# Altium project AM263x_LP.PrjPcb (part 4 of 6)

## Sheet PROC111_Ehernet_PHY_2.SchDoc
size 431 x 279 mm; Date: Not shown in title block; ApprovedBy: Not shown in title block; CheckedBy: Not shown in title block; Author: Not shown in title block; CompanyName: Not shown in title block; Engineer: Not shown in title block; Organization: Not shown in title block; Address1: Not shown in title block; Address2: Not shown in title block; Address3: Not shown in title block; Address4: Not shown in title block; DocumentNumber: 16; Revision: Use project parameter SCH_Rev; SheetNumber: 16; SheetTotal: 24; PageSetup: Record=PageOptions¦CenterHorizontal=True¦CenterVertical=True¦PrintScale=1.00¦XCorrection=1.00¦YCorrection=1.00¦PrintKind=0¦BorderSize=5000000¦LeftOffset=0¦BottomOffset=0¦Orientation=2¦PaperLength=1000¦PaperWidth=1000¦Scale=100¦PaperSource=15¦PrintQuality=600¦MediaType=1¦DitherType=10¦PaperKind=Letter¦PrintScaleMode=1
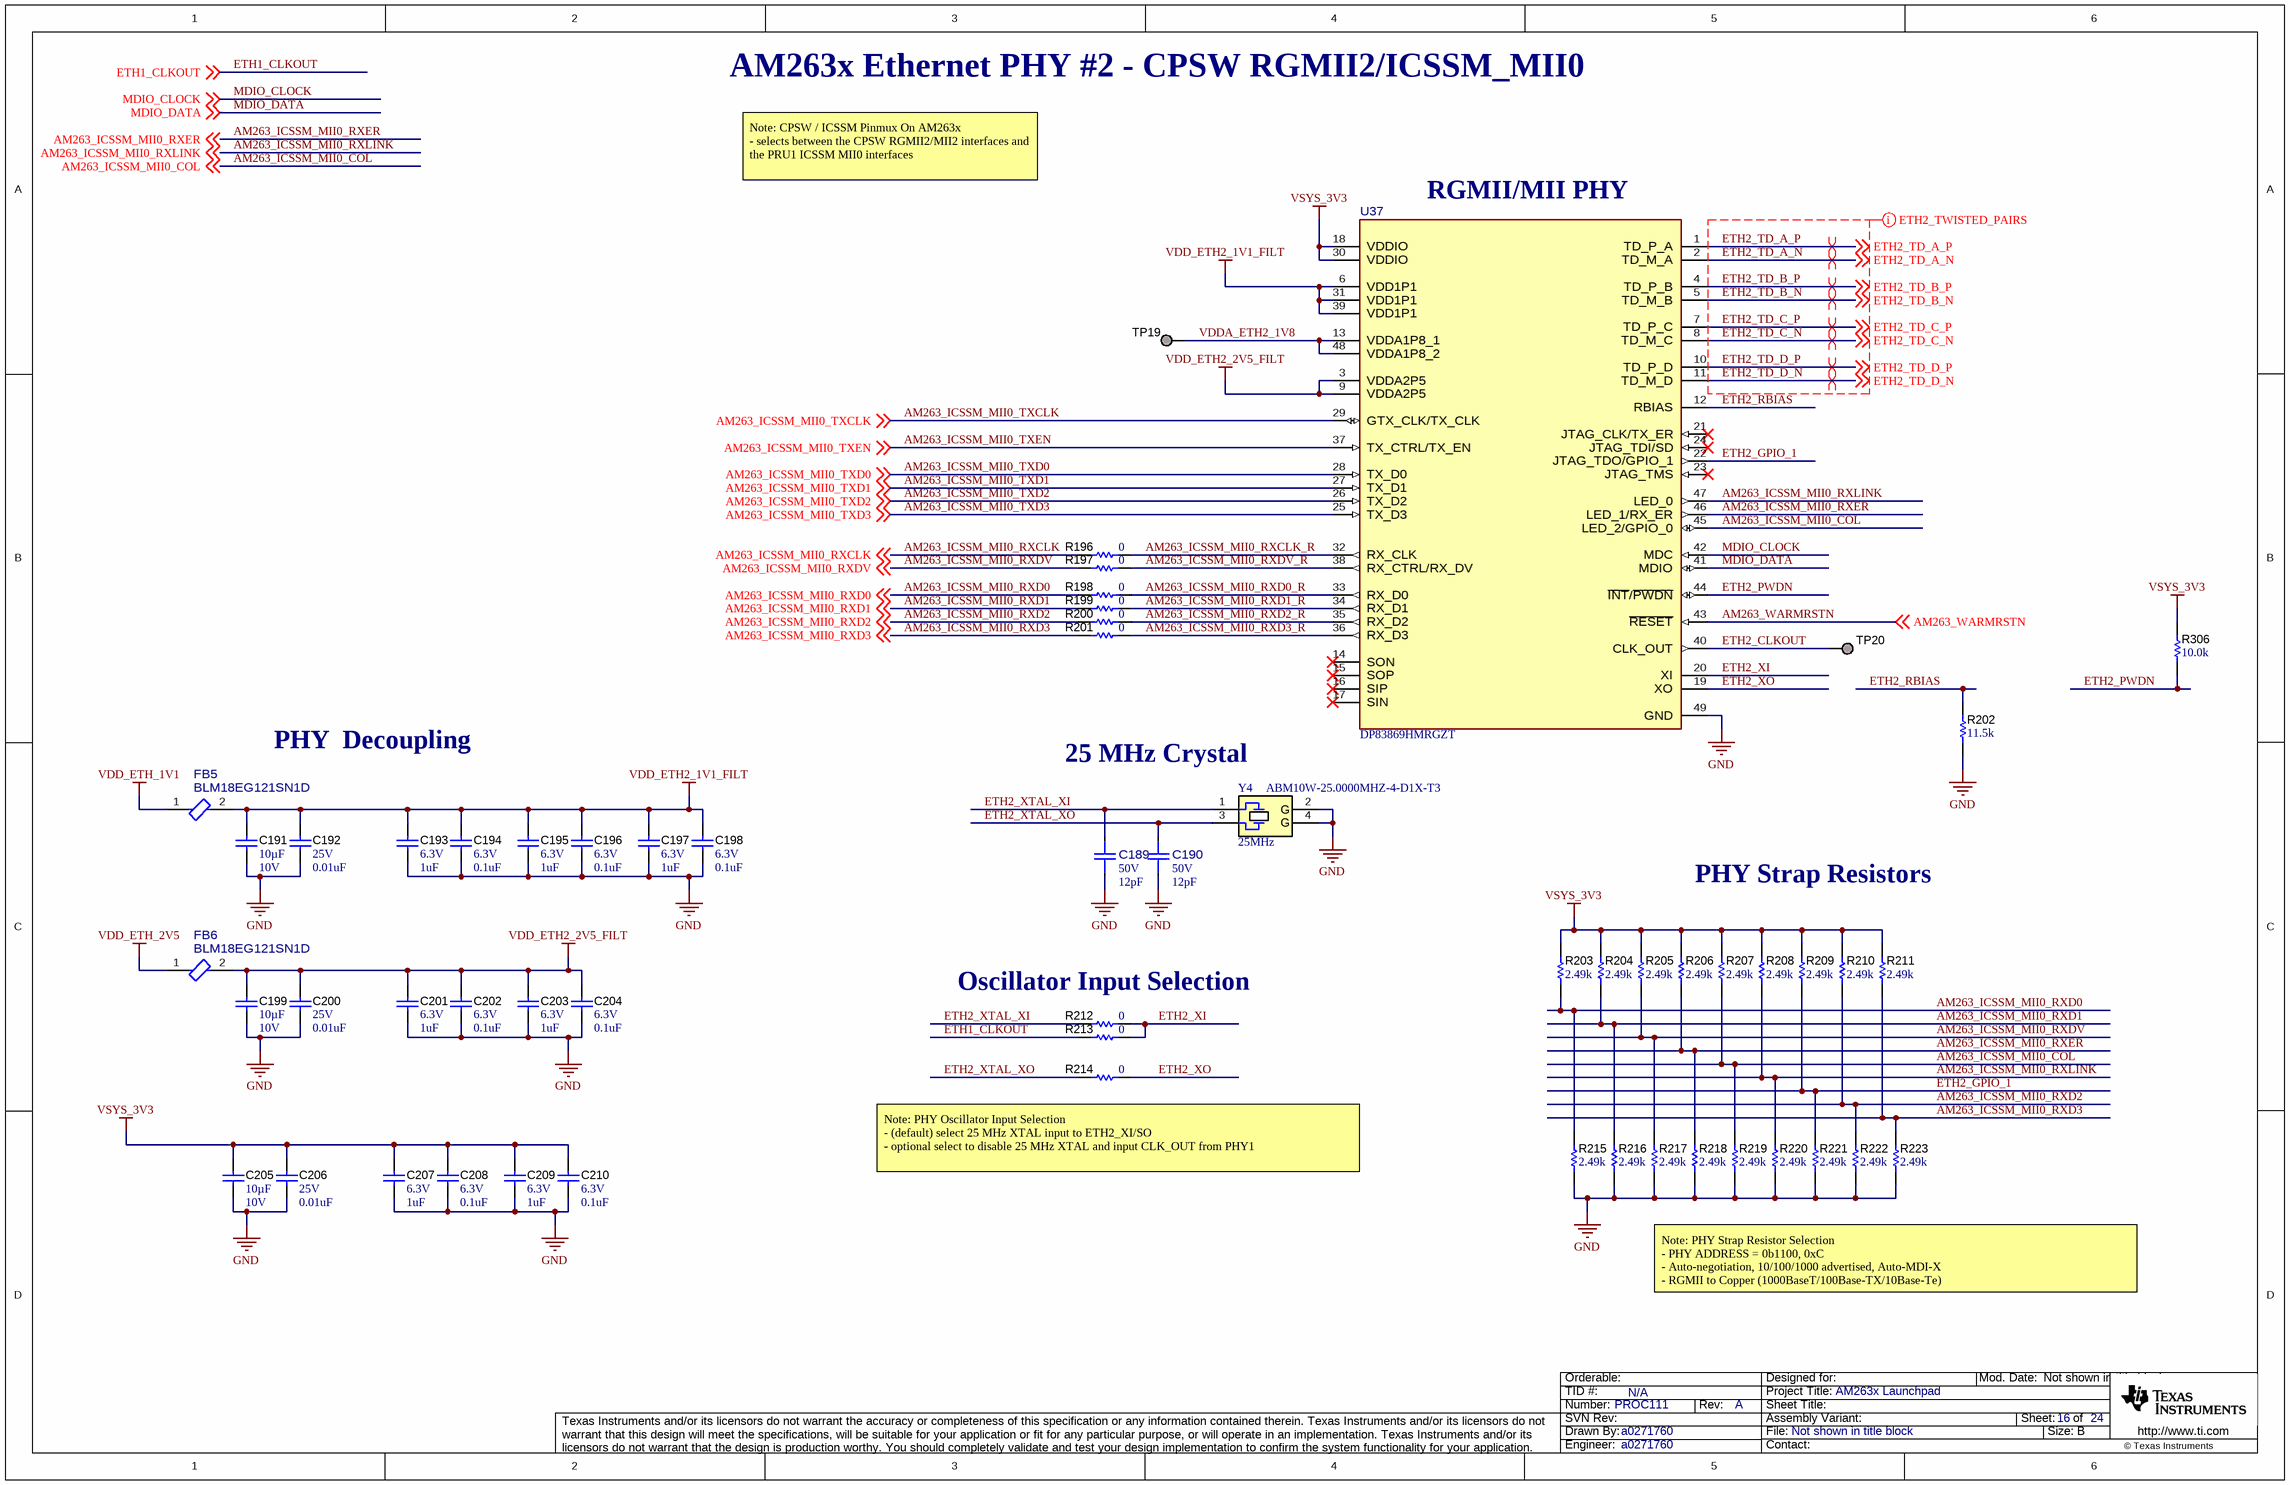
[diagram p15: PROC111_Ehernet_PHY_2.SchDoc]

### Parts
C189  VDC_V: 50V  ValueDisplayed: 12pF  [FP-GRT1555C1H120JA02D_0402-MFG]  (hidden comment: GRT1555C1H120JA02D)
C190  VDC_V: 50V  ValueDisplayed: 12pF  [FP-GRT1555C1H120JA02D_0402-MFG]  (hidden comment: GRT1555C1H120JA02D)
C191  Cap_F: 10µF  VDC_V: 10V  [0603]  (hidden comment: GRM188Z71A106MA73D)
C192  VDC_V: 25V  ValueDisplayed: 0.01uF  [0402]  (hidden comment: GRM155R71E103KA01D)
C193  VDC_V: 6.3V  ValueDisplayed: 1uF  [0402]  (hidden comment: GRM155R70J105MA12D)
C194  VDC_V: 6.3V  ValueDisplayed: 0.1uF  [0402]  (hidden comment: GRM155R70J104KA01D)
C195  VDC_V: 6.3V  ValueDisplayed: 1uF  [0402]  (hidden comment: GRM155R70J105MA12D)
C196  VDC_V: 6.3V  ValueDisplayed: 0.1uF  [0402]  (hidden comment: GRM155R70J104KA01D)
C197  VDC_V: 6.3V  ValueDisplayed: 1uF  [0402]  (hidden comment: GRM155R70J105MA12D)
C198  VDC_V: 6.3V  ValueDisplayed: 0.1uF  [0402]  (hidden comment: GRM155R70J104KA01D)
C199  Cap_F: 10µF  VDC_V: 10V  [0603]  (hidden comment: GRM188Z71A106MA73D)
C200  VDC_V: 25V  ValueDisplayed: 0.01uF  [0402]  (hidden comment: GRM155R71E103KA01D)
C201  VDC_V: 6.3V  ValueDisplayed: 1uF  [0402]  (hidden comment: GRM155R70J105MA12D)
C202  VDC_V: 6.3V  ValueDisplayed: 0.1uF  [0402]  (hidden comment: GRM155R70J104KA01D)
C203  VDC_V: 6.3V  ValueDisplayed: 1uF  [0402]  (hidden comment: GRM155R70J105MA12D)
C204  VDC_V: 6.3V  ValueDisplayed: 0.1uF  [0402]  (hidden comment: GRM155R70J104KA01D)
C205  Cap_F: 10µF  VDC_V: 10V  [0603]  (hidden comment: GRM188Z71A106MA73D)
C206  VDC_V: 25V  ValueDisplayed: 0.01uF  [0402]  (hidden comment: GRM155R71E103KA01D)
C207  VDC_V: 6.3V  ValueDisplayed: 1uF  [0402]  (hidden comment: GRM155R70J105MA12D)
C208  VDC_V: 6.3V  ValueDisplayed: 0.1uF  [0402]  (hidden comment: GRM155R70J104KA01D)
C209  VDC_V: 6.3V  ValueDisplayed: 1uF  [0402]  (hidden comment: GRM155R70J105MA12D)
C210  VDC_V: 6.3V  ValueDisplayed: 0.1uF  [0402]  (hidden comment: GRM155R70J104KA01D)
FB5  BLM18EG121SN1D  [FP-BLM18EG121SN1D_0603-MFG]
FB6  BLM18EG121SN1D  [FP-BLM18EG121SN1D_0603-MFG]
R196  ValueDisplayed: 0  [0402]  (hidden comment: ERJ-2GE0R00X)
R197  ValueDisplayed: 0  [0402]  (hidden comment: ERJ-2GE0R00X)
R198  ValueDisplayed: 0  [0402]  (hidden comment: ERJ-2GE0R00X)
R199  ValueDisplayed: 0  [0402]  (hidden comment: ERJ-2GE0R00X)
R200  ValueDisplayed: 0  [0402]  (hidden comment: ERJ-2GE0R00X)
R201  ValueDisplayed: 0  [0402]  (hidden comment: ERJ-2GE0R00X)
R202  ValueDisplayed: 11.5k  [0402]  (hidden comment: ERJ-2RKF1152X)
R203  ValueDisplayed: 2.49k  [0402]  (hidden comment: CRCW04022K49FKED)
R204  ValueDisplayed: 2.49k  [0402]  (hidden comment: CRCW04022K49FKED)
R205  ValueDisplayed: 2.49k  [0402]  (hidden comment: CRCW04022K49FKED)
R206  ValueDisplayed: 2.49k  [0402]  (hidden comment: CRCW04022K49FKED)
R207  ValueDisplayed: 2.49k  [0402]  (hidden comment: CRCW04022K49FKED)
R208  ValueDisplayed: 2.49k  [0402]  (hidden comment: CRCW04022K49FKED)
R209  ValueDisplayed: 2.49k  [0402]  (hidden comment: CRCW04022K49FKED)
R210  ValueDisplayed: 2.49k  [0402]  (hidden comment: CRCW04022K49FKED)
R211  ValueDisplayed: 2.49k  [0402]  (hidden comment: CRCW04022K49FKED)
R212  ValueDisplayed: 0  [0402]  (hidden comment: ERJ-2GE0R00X)
R213  ValueDisplayed: 0  [0402]  (hidden comment: ERJ-2GE0R00X)
R214  ValueDisplayed: 0  [0402]  (hidden comment: ERJ-2GE0R00X)
R215  ValueDisplayed: 2.49k  [0402]  (hidden comment: CRCW04022K49FKED)
R216  ValueDisplayed: 2.49k  [0402]  (hidden comment: CRCW04022K49FKED)
R217  ValueDisplayed: 2.49k  [0402]  (hidden comment: CRCW04022K49FKED)
R218  ValueDisplayed: 2.49k  [0402]  (hidden comment: CRCW04022K49FKED)
R219  ValueDisplayed: 2.49k  [0402]  (hidden comment: CRCW04022K49FKED)
R220  ValueDisplayed: 2.49k  [0402]  (hidden comment: CRCW04022K49FKED)
R221  ValueDisplayed: 2.49k  [0402]  (hidden comment: CRCW04022K49FKED)
R222  ValueDisplayed: 2.49k  [0402]  (hidden comment: CRCW04022K49FKED)
R223  ValueDisplayed: 2.49k  [0402]  (hidden comment: CRCW04022K49FKED)
R306  ValueDisplayed: 10.0k  [0402]  (hidden comment: ERJ-2RKF1002X)
TP19  TESTPOINT  [TP_25MIL-SMT]  (value not drawn)  (no BOM)
TP20  TESTPOINT  [TP_25MIL-SMT]  (value not drawn)  (no BOM)
U37  DP83869HMRGZT  [RGZ0048B-MFG]
Y4  Frequency_Fixed: 25MHz  [Abracon_ABM10W]  (hidden comment: ABM10W-25.0000MHZ-4-D1X-T3)

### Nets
GND: C189.1 C190.1 C191.2 C192.2 C193.2 C194.2 C195.2 C196.2 C197.2 C198.2 C199.2 C200.2 C201.2 C202.2 C203.2 C204.2 C205.2 C206.2 C207.2 C208.2 C209.2 C210.2 R202.1 R215.1 R216.1 R217.1 R218.1 R219.1 R220.1 R221.1 R222.1 R223.1 U37.49(GND) Y4.2(GND) Y4.4(GND)
VDD_ETH2_1V1_FILT: C191.1 C192.1 C193.1 C194.1 C195.1 C196.1 C197.1 C198.1 FB5.2 U37.6(VDD1P1) U37.31(VDD1P1) U37.39(VDD1P1)
VDD_ETH2_2V5_FILT: C199.1 C200.1 C201.1 C202.1 C203.1 C204.1 FB6.2 U37.3(VDDA2P5) U37.9(VDDA2P5)
VDD_ETH_1V1: FB5.1
VDD_ETH_2V5: FB6.1
VSYS_3V3: C205.1 C206.1 C207.1 C208.1 C209.1 C210.1 R203.2 R204.2 R205.2 R206.2 R207.2 R208.2 R209.2 R210.2 R211.2 R306.1 U37.18(VDDIO) U37.30(VDDIO)
AM263_ICSSM_MII0_COL: R207.1 R219.2 U37.45(LED_2/GPIO_0) ; off-sheet AM263_ICSSM_MII0_COL
AM263_ICSSM_MII0_RXCLK: R196.1 ; off-sheet AM263_ICSSM_MII0_RXCLK
AM263_ICSSM_MII0_RXCLK_R: R196.2 U37.32(RX_CLK)
AM263_ICSSM_MII0_RXD0: R198.1 R203.1 R215.2 ; off-sheet AM263_ICSSM_MII0_RXD0
AM263_ICSSM_MII0_RXD0_R: R198.2 U37.33(RX_D0)
AM263_ICSSM_MII0_RXD1: R199.1 R204.1 R216.2 ; off-sheet AM263_ICSSM_MII0_RXD1
AM263_ICSSM_MII0_RXD1_R: R199.2 U37.34(RX_D1)
AM263_ICSSM_MII0_RXD2: R200.1 R210.1 R222.2 ; off-sheet AM263_ICSSM_MII0_RXD2
AM263_ICSSM_MII0_RXD2_R: R200.2 U37.35(RX_D2)
AM263_ICSSM_MII0_RXD3: R201.1 R211.1 R223.2 ; off-sheet AM263_ICSSM_MII0_RXD3
AM263_ICSSM_MII0_RXD3_R: R201.2 U37.36(RX_D3)
AM263_ICSSM_MII0_RXDV: R197.1 R205.1 R217.2 ; off-sheet AM263_ICSSM_MII0_RXDV
AM263_ICSSM_MII0_RXDV_R: R197.2 U37.38(RX_CTRL/RX_DV)
AM263_ICSSM_MII0_RXER: R206.1 R218.2 U37.46(LED_1/RX_ER) ; off-sheet AM263_ICSSM_MII0_RXER
AM263_ICSSM_MII0_RXLINK: R208.1 R220.2 U37.47(LED_0) ; off-sheet AM263_ICSSM_MII0_RXLINK
AM263_ICSSM_MII0_TXCLK: U37.29(GTX_CLK/TX_CLK) ; off-sheet AM263_ICSSM_MII0_TXCLK
AM263_ICSSM_MII0_TXD0: U37.28(TX_D0) ; off-sheet AM263_ICSSM_MII0_TXD0
AM263_ICSSM_MII0_TXD1: U37.27(TX_D1) ; off-sheet AM263_ICSSM_MII0_TXD1
AM263_ICSSM_MII0_TXD2: U37.26(TX_D2) ; off-sheet AM263_ICSSM_MII0_TXD2
AM263_ICSSM_MII0_TXD3: U37.25(TX_D3) ; off-sheet AM263_ICSSM_MII0_TXD3
AM263_ICSSM_MII0_TXEN: U37.37(TX_CTRL/TX_EN) ; off-sheet AM263_ICSSM_MII0_TXEN
AM263_WARMRSTN: U37.43(~{RESET}) ; off-sheet AM263_WARMRSTN
ETH1_CLKOUT: R213.1 ; off-sheet ETH1_CLKOUT
ETH2_CLKOUT: TP20.1 U37.40(CLK_OUT)
ETH2_GPIO_1: R209.1 R221.2 U37.22(JTAG_TDO/GPIO_1)
ETH2_PWDN: R306.2 U37.44(~{INT}/~{PWDN})
ETH2_RBIAS: R202.2 U37.12(RBIAS)
ETH2_TD_A_N: U37.2(TD_M_A) ; off-sheet ETH2_TD_A_N
ETH2_TD_A_P: U37.1(TD_P_A) ; off-sheet ETH2_TD_A_P
ETH2_TD_B_N: U37.5(TD_M_B) ; off-sheet ETH2_TD_B_N
ETH2_TD_B_P: U37.4(TD_P_B) ; off-sheet ETH2_TD_B_P
ETH2_TD_C_N: U37.8(TD_M_C) ; off-sheet ETH2_TD_C_N
ETH2_TD_C_P: U37.7(TD_P_C) ; off-sheet ETH2_TD_C_P
ETH2_TD_D_N: U37.11(TD_M_D) ; off-sheet ETH2_TD_D_N
ETH2_TD_D_P: U37.10(TD_P_D) ; off-sheet ETH2_TD_D_P
ETH2_XI: R212.2 R213.2 U37.20(XI)
ETH2_XO: R214.2 U37.19(XO)
ETH2_XTAL_XI: C189.2 R212.1 Y4.1
ETH2_XTAL_XO: C190.2 R214.1 Y4.3
MDIO_CLOCK: U37.42(MDC) ; off-sheet MDIO_CLOCK
MDIO_DATA: U37.41(MDIO) ; off-sheet MDIO_DATA
VDDA_ETH2_1V8: TP19.1 U37.13(VDDA1P8_1) U37.48(VDDA1P8_2)

Not connected (* = marked no-connect by the designer): U37 14(SON)* 15(SOP)* 16(SIP)* 17(SIN)* 21(JTAG_CLK/TX_ER)* 23(JTAG_TMS)* 24(JTAG_TDI/SD)*

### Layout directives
differential pair: ETH2_TD_A_N, ETH2_TD_A_P, ETH2_TD_B_N, ETH2_TD_B_P, ETH2_TD_C_N, ETH2_TD_C_P, ETH2_TD_D_N, ETH2_TD_D_P
mark named ETH2_TWISTED_PAIRS: ETH2_TD_A_N, ETH2_TD_A_P, ETH2_TD_B_N, ETH2_TD_B_P, ETH2_TD_C_N, ETH2_TD_C_P, ETH2_TD_D_N, ETH2_TD_D_P

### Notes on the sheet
- AM263x Ethernet PHY #2 - CPSW RGMII2/ICSSM_MII0
- Note: CPSW / ICSSM Pinmux On AM263x
  - selects between the CPSW RGMII2/MII2 interfaces and the PRU1 ICSSM MII0 interfaces
- (near U37) RGMII/MII PHY
- PHY  Decoupling
- (near Y4) 25 MHz Crystal
- PHY Strap Resistors
- Oscillator Input Selection
- (near R214) Note: PHY Oscillator Input Selection
  - (default) select 25 MHz XTAL input to ETH2_XI/SO
  - optional select to disable 25 MHz XTAL and input CLK_OUT from PHY1
- Note: PHY Strap Resistor Selection
  - PHY ADDRESS = 0b1100, 0xC
  - Auto-negotiation, 10/100/1000 advertised, Auto-MDI-X
  - RGMII to Copper (1000BaseT/100Base-TX/10Base-Te)

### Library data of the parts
C189 C190 = CMP-0120209-1: Multi-Layer Ceramic Capacitor 12pF 50V C0G ±5% 0402 Paper T/R; Manufacturer: Murata; TempCo: 30ppm/°C; SizeZ_mm: 0.55mm; AEC Qualified: Yes; AEC Grade: Grade 1
C191 C199 C205 = CMP-0007497-5: CAP, CERM, 10 uF, 10 V, +/- 20%, X7R, 0603; Manufacturer: MuRata; TaMin_C: -55°C; Polarized: N; SizeAreaWB_mm2: 4.68; Value1: Unknown; U/M: EA; Value: 10uF; TaMax_C: 125°C; SizeZ_mm: 1; SizeX_mm: 1.6; SizeY_mm: 0.8; SizeArea_mm2: 1.28; AEC Category: Q200
C192 C200 C206 = CMP-0006658-2: CAP, CERM, 0.01 uF, 25 V, +/- 10%, X7R, 0402; Manufacturer: MuRata; TaMin_C: -55°C; Polarized: N; SizeAreaWB_mm2: 3; Value1: Unknown; U/M: EA; Value: 0.01uF; TaMax_C: 125°C; SizeZ_mm: 0.6; SizeX_mm: 1; SizeY_mm: 0.5; Cap_F: 10nF; AEC Category: Q200
C193 C195 C197 C201 C203 C207 C209 = CMP-0006624-2: CAP, CERM, 1 uF, 6.3 V, +/- 20%, X7R, 0402; Manufacturer: MuRata; TaMin_C: -55°C; Polarized: N; SizeAreaWB_mm2: 3; Value1: Unknown; U/M: EA; Value: 1uF; TaMax_C: 125°C; SizeZ_mm: 0.6; SizeX_mm: 1; SizeY_mm: 0.5; Cap_F: 1µF; AEC Category: Q200
C194 C196 C198 C202 C204 C208 C210 = CMP-0006623-2: CAP, CERM, 0.1 uF, 6.3 V, +/- 10%, X7R, 0402; Manufacturer: MuRata; TaMin_C: -55°C; Polarized: N; SizeAreaWB_mm2: 3; Value1: Unknown; U/M: EA; Value: 0.1uF; TaMax_C: 125°C; SizeZ_mm: 0.6; SizeX_mm: 1; SizeY_mm: 0.5; Cap_F: 100nF; AEC Category: Q200
FB5 FB6 = CMP-0089199-1: 120 Ohms @ 100MHz 1  Ferrite Bead 0603 (1608 Metric) 2A 40mOhm; Manufacturer: Murata; DCR_ohm: 60m; AEC Qualified: No; Tolerance_%: 25%; SizeZ_mm: 0.95mm; Impedance At Frequency: 120Ω @ 100MHz
R196-R201 R212-R214 = CMP-0026992-3: RES, 0, 5%, 0.1 W, AEC-Q200 Grade 0, 0402; Manufacturer: Panasonic; Power_W: 100mW; TempCo: 600 ppm/C; Value_Code: 0000; Value: 0; EIA_Code: E24; SizeX_mm: 1; SizeY_mm: 0.5; SizeZ_mm: 0.6; Value2: 0.1W; AEC Qualified: Y; VDC_V: 50V; AEC Category: Q200; SizeAreaWB_mm2: 3
R202 = CMP-0082348-1: RES, 11.5 k, 1%, 0.1 W, AEC-Q200 Grade 0, 0402; Manufacturer: Panasonic; Value_Code: 11k5; SizeAreaWB_mm2: 3; SizeArea_mm2: 0.5; AEC Qualified: Y; AEC Category: Q200; Value: 11.5k; SizeZ_mm: 0.6; EIA_Code: E96; TempCo: 100 ppm/C; AEC Grade: 0; Power_W: 100mW; Value2: 0.1W; SizeX_mm: 1
R203-R211 R215-R223 = CMP-0026237-2: RES, 2.49 k, 1%, 0.063 W, AEC-Q200 Grade 0, 0402; Manufacturer: Vishay-Dale; Power_W: 63mW; TempCo: 100 ppm/C; Value_Code: 2k49; Value: 2.49k; EIA_Code: E96; SizeX_mm: 1; SizeY_mm: 0.5; SizeZ_mm: 0.6; Value2: 0.063W; AEC Qualified: Y; VDC_V: 50V; AEC Category: Q200; AEC Grade: 0
R306 = CMP-0026658-1: RES, 10.0 k, 1%, 0.1 W, 0402; Manufacturer: Panasonic; Power_W: 100mW; TempCo: 100 ppm/C; Value_Code: 10k0; U/M: EA; Value: 10.0k; EIA_Code: E96; Res_ohm: 10k; SizeX_mm: 1; SizeY_mm: 0.5; SizeZ_mm: 0.6; Value2: 0.1W; VDC_V: 50V; AEC Category: Q200
TP19 TP20 = CMP-0078143-3: TEST POINT.  No entry in BOM.
U37 = CMP-0091377-1: 1/1 Transceiver Ethernet 48-VQFN (7x7); Manufacturer: Texas Instruments; TaMin_C: -40°C; SizeZ_mm: 1mm; TaMax_C: +125°C; Max Supply Voltage: 3.45V; Number Of Channels: 1; AEC Qualified: No; Data Rate: 1000Mbits/s; Min Supply Voltage: 990mV; Simplex Duplex: Full-Duplex; Standoff Height: 0mm
Y4 = CMP-0084811-1: Crystal, 25 MHz, 10 ppm, 4 pF, SMD; Manufacturer: Abracon Corporation; Load Capacitance: 4 pF; TaMax_C: 85°C; SizeY_mm: 2.5; SizeAreaWB_mm2: 10.5; AEC Category: Q200; Frequency Stability: 20 ppm; SizeX_mm: 2; SizeArea_mm2: 5; SizeZ_mm: 0.6; AEC Qualified: N; TaMin_C: -40°C; Frequency Tolerance: 10 ppm

## Sheet PROC111_Ehernet_RJ45_1.SchDoc
size 431 x 279 mm; Date: Not shown in title block; ApprovedBy: Not shown in title block; CheckedBy: Not shown in title block; Author: Not shown in title block; CompanyName: Not shown in title block; Engineer: Not shown in title block; Organization: Not shown in title block; Address1: Not shown in title block; Address2: Not shown in title block; Address3: Not shown in title block; Address4: Not shown in title block; DocumentNumber: 17; Revision: Use project parameter SCH_Rev; SheetNumber: 17; SheetTotal: 24; PageSetup: Record=PageOptions¦CenterHorizontal=True¦CenterVertical=True¦PrintScale=1.00¦XCorrection=1.00¦YCorrection=1.00¦PrintKind=0¦BorderSize=5000000¦LeftOffset=0¦BottomOffset=0¦Orientation=2¦PaperLength=1000¦PaperWidth=1000¦Scale=100¦PaperSource=15¦PrintQuality=600¦MediaType=1¦DitherType=10¦PaperKind=Letter¦PrintScaleMode=1
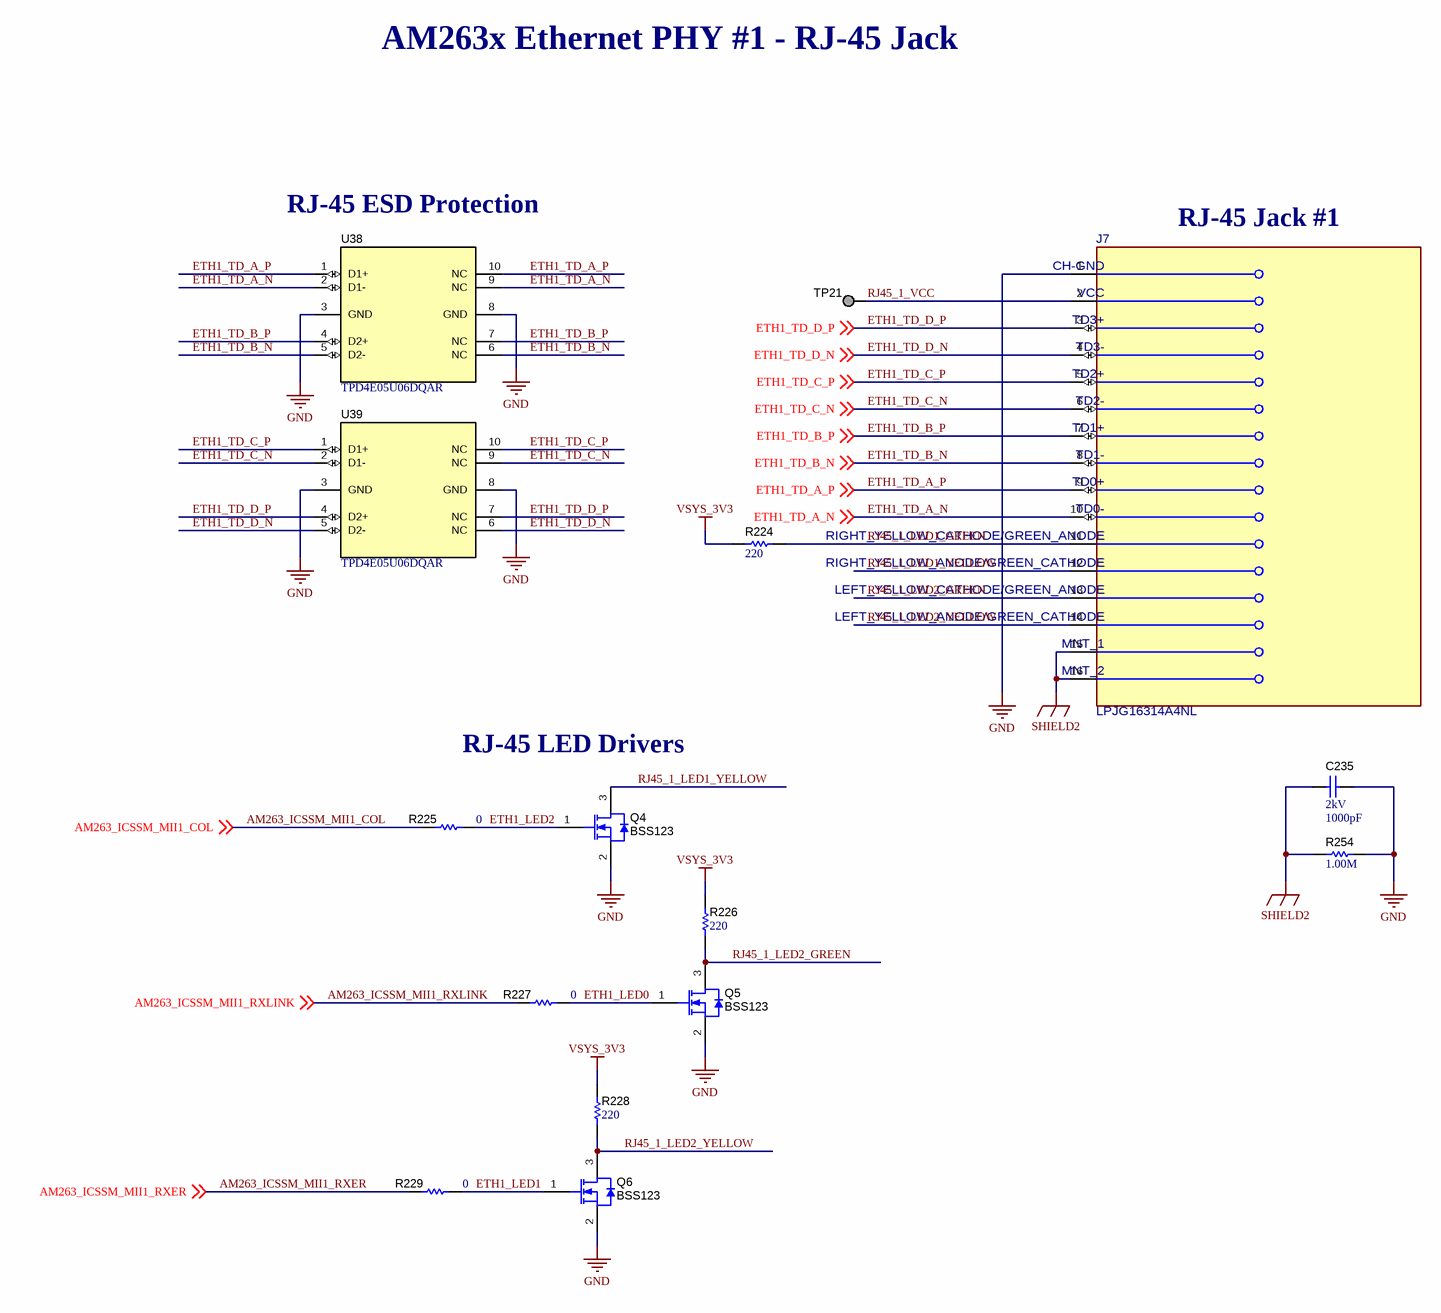
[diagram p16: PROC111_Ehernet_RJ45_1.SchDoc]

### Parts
C235  VDC_V: 2kV  ValueDisplayed: 1000pF  [1808]  (hidden comment: GR442QR73D102KW01L)
J7  LPJG16314A4NL  [FP-LPJG16314A4NL_CONN_RJ45-MFG]
Q4  BSS123  [SOT-23]
Q5  BSS123  [SOT-23]
Q6  BSS123  [SOT-23]
R224  ValueDisplayed: 220  [0402]  (hidden comment: CRCW0402220RJNED)
R225  ValueDisplayed: 0  [0402L]  (hidden comment: ERJ-2GE0R00X)
R226  ValueDisplayed: 220  [0402]  (hidden comment: CRCW0402220RJNED)
R227  ValueDisplayed: 0  [0402L]  (hidden comment: ERJ-2GE0R00X)
R228  ValueDisplayed: 220  [0402]  (hidden comment: CRCW0402220RJNED)
R229  ValueDisplayed: 0  [0402L]  (hidden comment: ERJ-2GE0R00X)
R254  ValueDisplayed: 1.00M  [0805_HV]  (hidden comment: ERJ-6ENF1004V)
TP21  TESTPOINT  [TP_25MIL-SMT]  (value not drawn)  (no BOM)
U38  TPD4E05U06DQAR  [DQA0010A]
U39  TPD4E05U06DQAR  [DQA0010A]

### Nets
GND: C235.1 J7.1(CH-GND) Q4.2(S) Q5.2(S) Q6.2(S) R254.2 U38.3(GND) U38.8(GND) U39.3(GND) U39.8(GND)
SHIELD2: C235.2 J7.15(MNT_1) J7.16(MNT_2) R254.1
VSYS_3V3: R224.1 R226.2 R228.2
AM263_ICSSM_MII1_COL: R225.2 ; off-sheet AM263_ICSSM_MII1_COL
AM263_ICSSM_MII1_RXER: R229.2 ; off-sheet AM263_ICSSM_MII1_RXER
AM263_ICSSM_MII1_RXLINK: R227.2 ; off-sheet AM263_ICSSM_MII1_RXLINK
ETH1_LED0: Q5.1(G) R227.1
ETH1_LED1: Q6.1(G) R229.1
ETH1_LED2: Q4.1(G) R225.1
ETH1_TD_A_N: J7.10(TD0-) U38.2(D1-) U38.9(NC) ; off-sheet ETH1_TD_A_N
ETH1_TD_A_P: J7.9(TD0+) U38.1(D1+) U38.10(NC) ; off-sheet ETH1_TD_A_P
ETH1_TD_B_N: J7.8(TD1-) U38.5(D2-) U38.6(NC) ; off-sheet ETH1_TD_B_N
ETH1_TD_B_P: J7.7(TD1+) U38.4(D2+) U38.7(NC) ; off-sheet ETH1_TD_B_P
ETH1_TD_C_N: J7.6(TD2-) U39.2(D1-) U39.9(NC) ; off-sheet ETH1_TD_C_N
ETH1_TD_C_P: J7.5(TD2+) U39.1(D1+) U39.10(NC) ; off-sheet ETH1_TD_C_P
ETH1_TD_D_N: J7.4(TD3-) U39.5(D2-) U39.6(NC) ; off-sheet ETH1_TD_D_N
ETH1_TD_D_P: J7.3(TD3+) U39.4(D2+) U39.7(NC) ; off-sheet ETH1_TD_D_P
RJ45_1_LED1_GREEN: J7.11(RIGHT_YELLOW_CATHODE/GREEN_ANODE) R224.2
RJ45_1_LED1_YELLOW: J7.12(RIGHT_YELLOW_ANODE/GREEN_CATHODE) Q4.3(D)
RJ45_1_LED2_GREEN: J7.13(LEFT_YELLOW_CATHODE/GREEN_ANODE) Q5.3(D) R226.1
RJ45_1_LED2_YELLOW: J7.14(LEFT_YELLOW_ANODE/GREEN_CATHODE) Q6.3(D) R228.1
RJ45_1_VCC: J7.2(VCC) TP21.1

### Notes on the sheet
- AM263x Ethernet PHY #1 - RJ-45 Jack
- RJ-45 ESD Protection
- RJ-45 Jack #1
- RJ-45 LED Drivers

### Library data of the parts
C235 = CMP-0009436-2: CAP, CERM, 1000 pF, 2000 V, +/- 10%, X7R, 1808; Manufacturer: MuRata; TaMin_C: -55°C; Polarized: N; SizeAreaWB_mm2: 16.5; Value1: Unknown; U/M: EA; Value: 1000pF; TaMax_C: 125°C; SizeZ_mm: 2.03; SizeX_mm: 4.5; SizeY_mm: 2; Value2: 2000V; SizeArea_mm2: 9; Cap_F: 1nF; AEC Category: Q200
J7 = CMP-0093483-1: RJ45 Connector with 1000 Base-TX Inetgrated Magnetic; Manufacturer: Link-PP; SizeZ_mm: 13.7mm; AEC Qualified: No; DUT-Pitch_mm: 1.27mm; Conn Gender: Female; Is Female: yes; ContactFinish: Gold; Conn Orientation: Horizontal
Q4-Q6 = CMP-0000947-2: MOSFET, N-CH, 100 V, 0.17 A, SOT-23; Alternate Manufacturer: None; Manufacturer: Fairchild Semiconductor; SizeZ_mm: 1.1; ChType: N; Value2: 1.8 nC; Value1: 1; VdsMax_V: 100V; SizeX_mm: 2.5; SizeY_mm: 3; Vgs_V: 20V; Value: 100V; Rdson45_ohm: 10; SizeArea_mm2: 7.5; AEC Category: Q101; IdsMax_A: 1.7dA; SizeAreaWB_mm2: 14; U/M: EA; QgTyp_nC: 1.8
R224 R226 R228 = CMP-0026878-3: RES, 220, 5%, 0.063 W, AEC-Q200 Grade 0, 0402; Manufacturer: Vishay-Dale; Power_W: 63mW; TempCo: 200 ppm/C; Value_Code: 220R; Value: 220; EIA_Code: E24; SizeX_mm: 1; SizeY_mm: 0.5; SizeZ_mm: 0.6; Value2: 0.063W; AEC Qualified: Y; VDC_V: 50V; AEC Category: Q200; AEC Grade: 0
R225 R227 R229 = CMP-0026992-3: as R196-R201 on sheet PROC111_Ehernet_PHY_2
R254 = CMP-0021522-3: RES, 1.00 M, 1%, 0.125 W, AEC-Q200 Grade 0, 0805; Manufacturer: Panasonic; Power_W: 125mW; TempCo: 100 ppm/C; Value_Code: 1M00; Value: 1.00Meg; EIA_Code: E96; Res_ohm: 1M; SizeX_mm: 2; SizeY_mm: 1.25; SizeZ_mm: 1.45; Value2: 0.125W; SizeArea_mm2: 2.5; AEC Qualified: Y; AEC Category: Q200; AEC Grade: 0; SizeAreaWB_mm2: 6.75
TP21 = CMP-0078143-3: TEST POINT.  No entry in BOM.
U38 U39 = CMP-0073613-3: 4-Channel Ultra-Low-Capacitance IEC ESD Protection Diode, DQA0010A (USON-10); Alternate Manufacturer: Texas Instruments; Green_Lifecycle: Active; SizeAreaWB_mm2: 7.0; Green_REACh: Passed; SizeZ_mm: 0.55; SizeX_mm: 1.0; SizeY_mm: 2.5; CompType: IC; AEC Category: Q200; AEC Qualified: N

## Sheet PROC111_Ehernet_RJ45_2.SchDoc
size 431 x 279 mm; Date: Not shown in title block; ApprovedBy: Not shown in title block; CheckedBy: Not shown in title block; Author: Not shown in title block; CompanyName: Not shown in title block; Engineer: Not shown in title block; Organization: Not shown in title block; Address1: Not shown in title block; Address2: Not shown in title block; Address3: Not shown in title block; Address4: Not shown in title block; DocumentNumber: 18; Revision: Use project parameter SCH_Rev; SheetNumber: 18; SheetTotal: 24; PageSetup: Record=PageOptions¦CenterHorizontal=True¦CenterVertical=True¦PrintScale=1.00¦XCorrection=1.00¦YCorrection=1.00¦PrintKind=0¦BorderSize=5000000¦LeftOffset=0¦BottomOffset=0¦Orientation=2¦PaperLength=1000¦PaperWidth=1000¦Scale=100¦PaperSource=15¦PrintQuality=600¦MediaType=1¦DitherType=10¦PaperKind=Letter¦PrintScaleMode=1
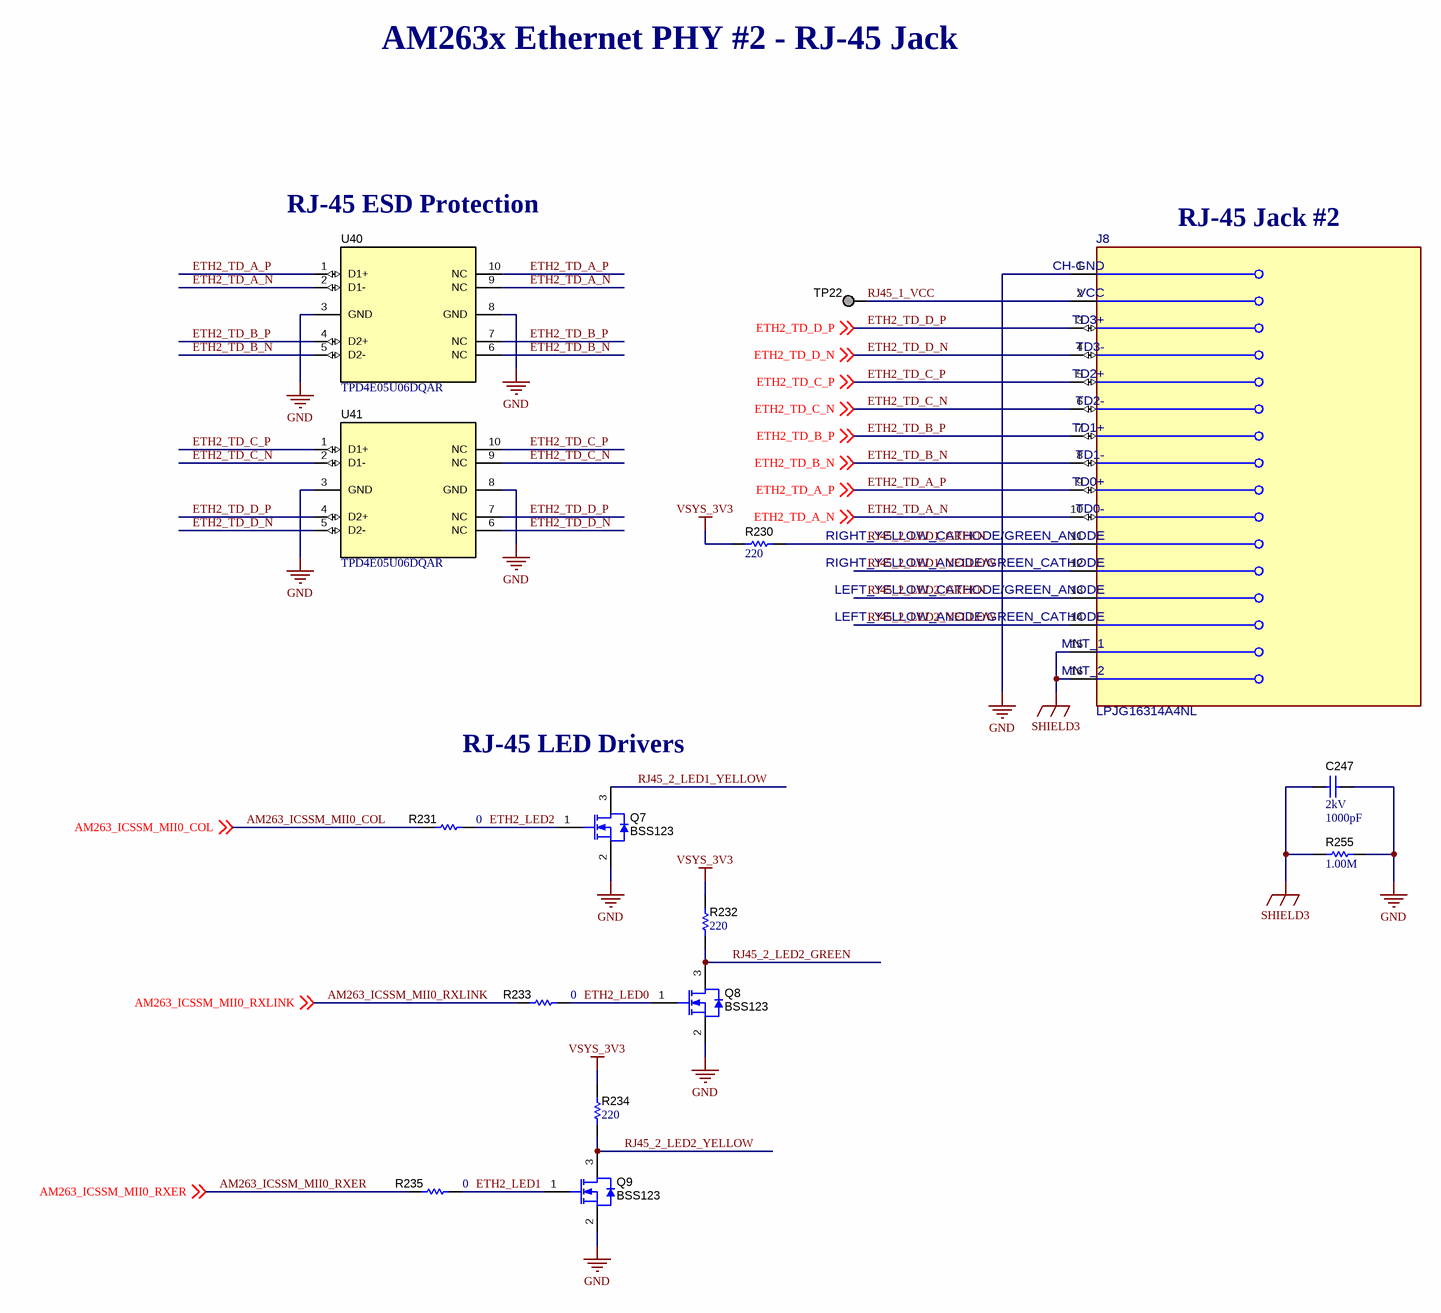
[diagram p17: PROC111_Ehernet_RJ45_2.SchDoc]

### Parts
C247  VDC_V: 2kV  ValueDisplayed: 1000pF  [1808]  (hidden comment: GR442QR73D102KW01L)
J8  LPJG16314A4NL  [FP-LPJG16314A4NL_CONN_RJ45-MFG]
Q7  BSS123  [SOT-23]
Q8  BSS123  [SOT-23]
Q9  BSS123  [SOT-23]
R230  ValueDisplayed: 220  [0402]  (hidden comment: CRCW0402220RJNED)
R231  ValueDisplayed: 0  [0402L]  (hidden comment: ERJ-2GE0R00X)
R232  ValueDisplayed: 220  [0402]  (hidden comment: CRCW0402220RJNED)
R233  ValueDisplayed: 0  [0402L]  (hidden comment: ERJ-2GE0R00X)
R234  ValueDisplayed: 220  [0402]  (hidden comment: CRCW0402220RJNED)
R235  ValueDisplayed: 0  [0402L]  (hidden comment: ERJ-2GE0R00X)
R255  ValueDisplayed: 1.00M  [0805_HV]  (hidden comment: ERJ-6ENF1004V)
TP22  TESTPOINT  [TP_25MIL-SMT]  (value not drawn)  (no BOM)
U40  TPD4E05U06DQAR  [DQA0010A]
U41  TPD4E05U06DQAR  [DQA0010A]

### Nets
GND: C247.1 J8.1(CH-GND) Q7.2(S) Q8.2(S) Q9.2(S) R255.2 U40.3(GND) U40.8(GND) U41.3(GND) U41.8(GND)
SHIELD3: C247.2 J8.15(MNT_1) J8.16(MNT_2) R255.1
VSYS_3V3: R230.1 R232.2 R234.2
AM263_ICSSM_MII0_COL: R231.2 ; off-sheet AM263_ICSSM_MII0_COL
AM263_ICSSM_MII0_RXER: R235.2 ; off-sheet AM263_ICSSM_MII0_RXER
AM263_ICSSM_MII0_RXLINK: R233.2 ; off-sheet AM263_ICSSM_MII0_RXLINK
ETH2_LED0: Q8.1(G) R233.1
ETH2_LED1: Q9.1(G) R235.1
ETH2_LED2: Q7.1(G) R231.1
ETH2_TD_A_N: J8.10(TD0-) U40.2(D1-) U40.9(NC) ; off-sheet ETH2_TD_A_N
ETH2_TD_A_P: J8.9(TD0+) U40.1(D1+) U40.10(NC) ; off-sheet ETH2_TD_A_P
ETH2_TD_B_N: J8.8(TD1-) U40.5(D2-) U40.6(NC) ; off-sheet ETH2_TD_B_N
ETH2_TD_B_P: J8.7(TD1+) U40.4(D2+) U40.7(NC) ; off-sheet ETH2_TD_B_P
ETH2_TD_C_N: J8.6(TD2-) U41.2(D1-) U41.9(NC) ; off-sheet ETH2_TD_C_N
ETH2_TD_C_P: J8.5(TD2+) U41.1(D1+) U41.10(NC) ; off-sheet ETH2_TD_C_P
ETH2_TD_D_N: J8.4(TD3-) U41.5(D2-) U41.6(NC) ; off-sheet ETH2_TD_D_N
ETH2_TD_D_P: J8.3(TD3+) U41.4(D2+) U41.7(NC) ; off-sheet ETH2_TD_D_P
RJ45_1_VCC: J8.2(VCC) TP22.1
RJ45_2_LED1_GREEN: J8.11(RIGHT_YELLOW_CATHODE/GREEN_ANODE) R230.2
RJ45_2_LED1_YELLOW: J8.12(RIGHT_YELLOW_ANODE/GREEN_CATHODE) Q7.3(D)
RJ45_2_LED2_GREEN: J8.13(LEFT_YELLOW_CATHODE/GREEN_ANODE) Q8.3(D) R232.1
RJ45_2_LED2_YELLOW: J8.14(LEFT_YELLOW_ANODE/GREEN_CATHODE) Q9.3(D) R234.1

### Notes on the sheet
- AM263x Ethernet PHY #2 - RJ-45 Jack
- RJ-45 ESD Protection
- RJ-45 Jack #2
- RJ-45 LED Drivers

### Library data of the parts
C247 = CMP-0009436-2: as C235 on sheet PROC111_Ehernet_RJ45_1
J8 = CMP-0093483-1: as J7 on sheet PROC111_Ehernet_RJ45_1
Q7-Q9 = CMP-0000947-2: as Q4 on sheet PROC111_Ehernet_RJ45_1
R230 R232 R234 = CMP-0026878-3: as R224 on sheet PROC111_Ehernet_RJ45_1
R231 R233 R235 = CMP-0026992-3: as R196-R201 on sheet PROC111_Ehernet_PHY_2
R255 = CMP-0021522-3: as R254 on sheet PROC111_Ehernet_RJ45_1
TP22 = CMP-0078143-3: TEST POINT.  No entry in BOM.
U40 U41 = CMP-0073613-3: as U38 on sheet PROC111_Ehernet_RJ45_1

## Sheet PROC111_Boosterpack_Headers.SchDoc
size 431 x 279 mm; Date: Not shown in title block; ApprovedBy: Not shown in title block; CheckedBy: Not shown in title block; Author: Not shown in title block; CompanyName: Not shown in title block; Engineer: Not shown in title block; Organization: Not shown in title block; Address1: Not shown in title block; Address2: Not shown in title block; Address3: Not shown in title block; Address4: Not shown in title block; DocumentNumber: 19; Revision: Use project parameter SCH_Rev; SheetNumber: 19; SheetTotal: 24; PageSetup: Record=PageOptions¦CenterHorizontal=True¦CenterVertical=True¦PrintScale=1.00¦XCorrection=1.00¦YCorrection=1.00¦PrintKind=0¦BorderSize=5000000¦LeftOffset=0¦BottomOffset=0¦Orientation=2¦PaperLength=1000¦PaperWidth=1000¦Scale=100¦PaperSource=15¦PrintQuality=600¦MediaType=1¦DitherType=10¦PaperKind=Letter¦PrintScaleMode=1
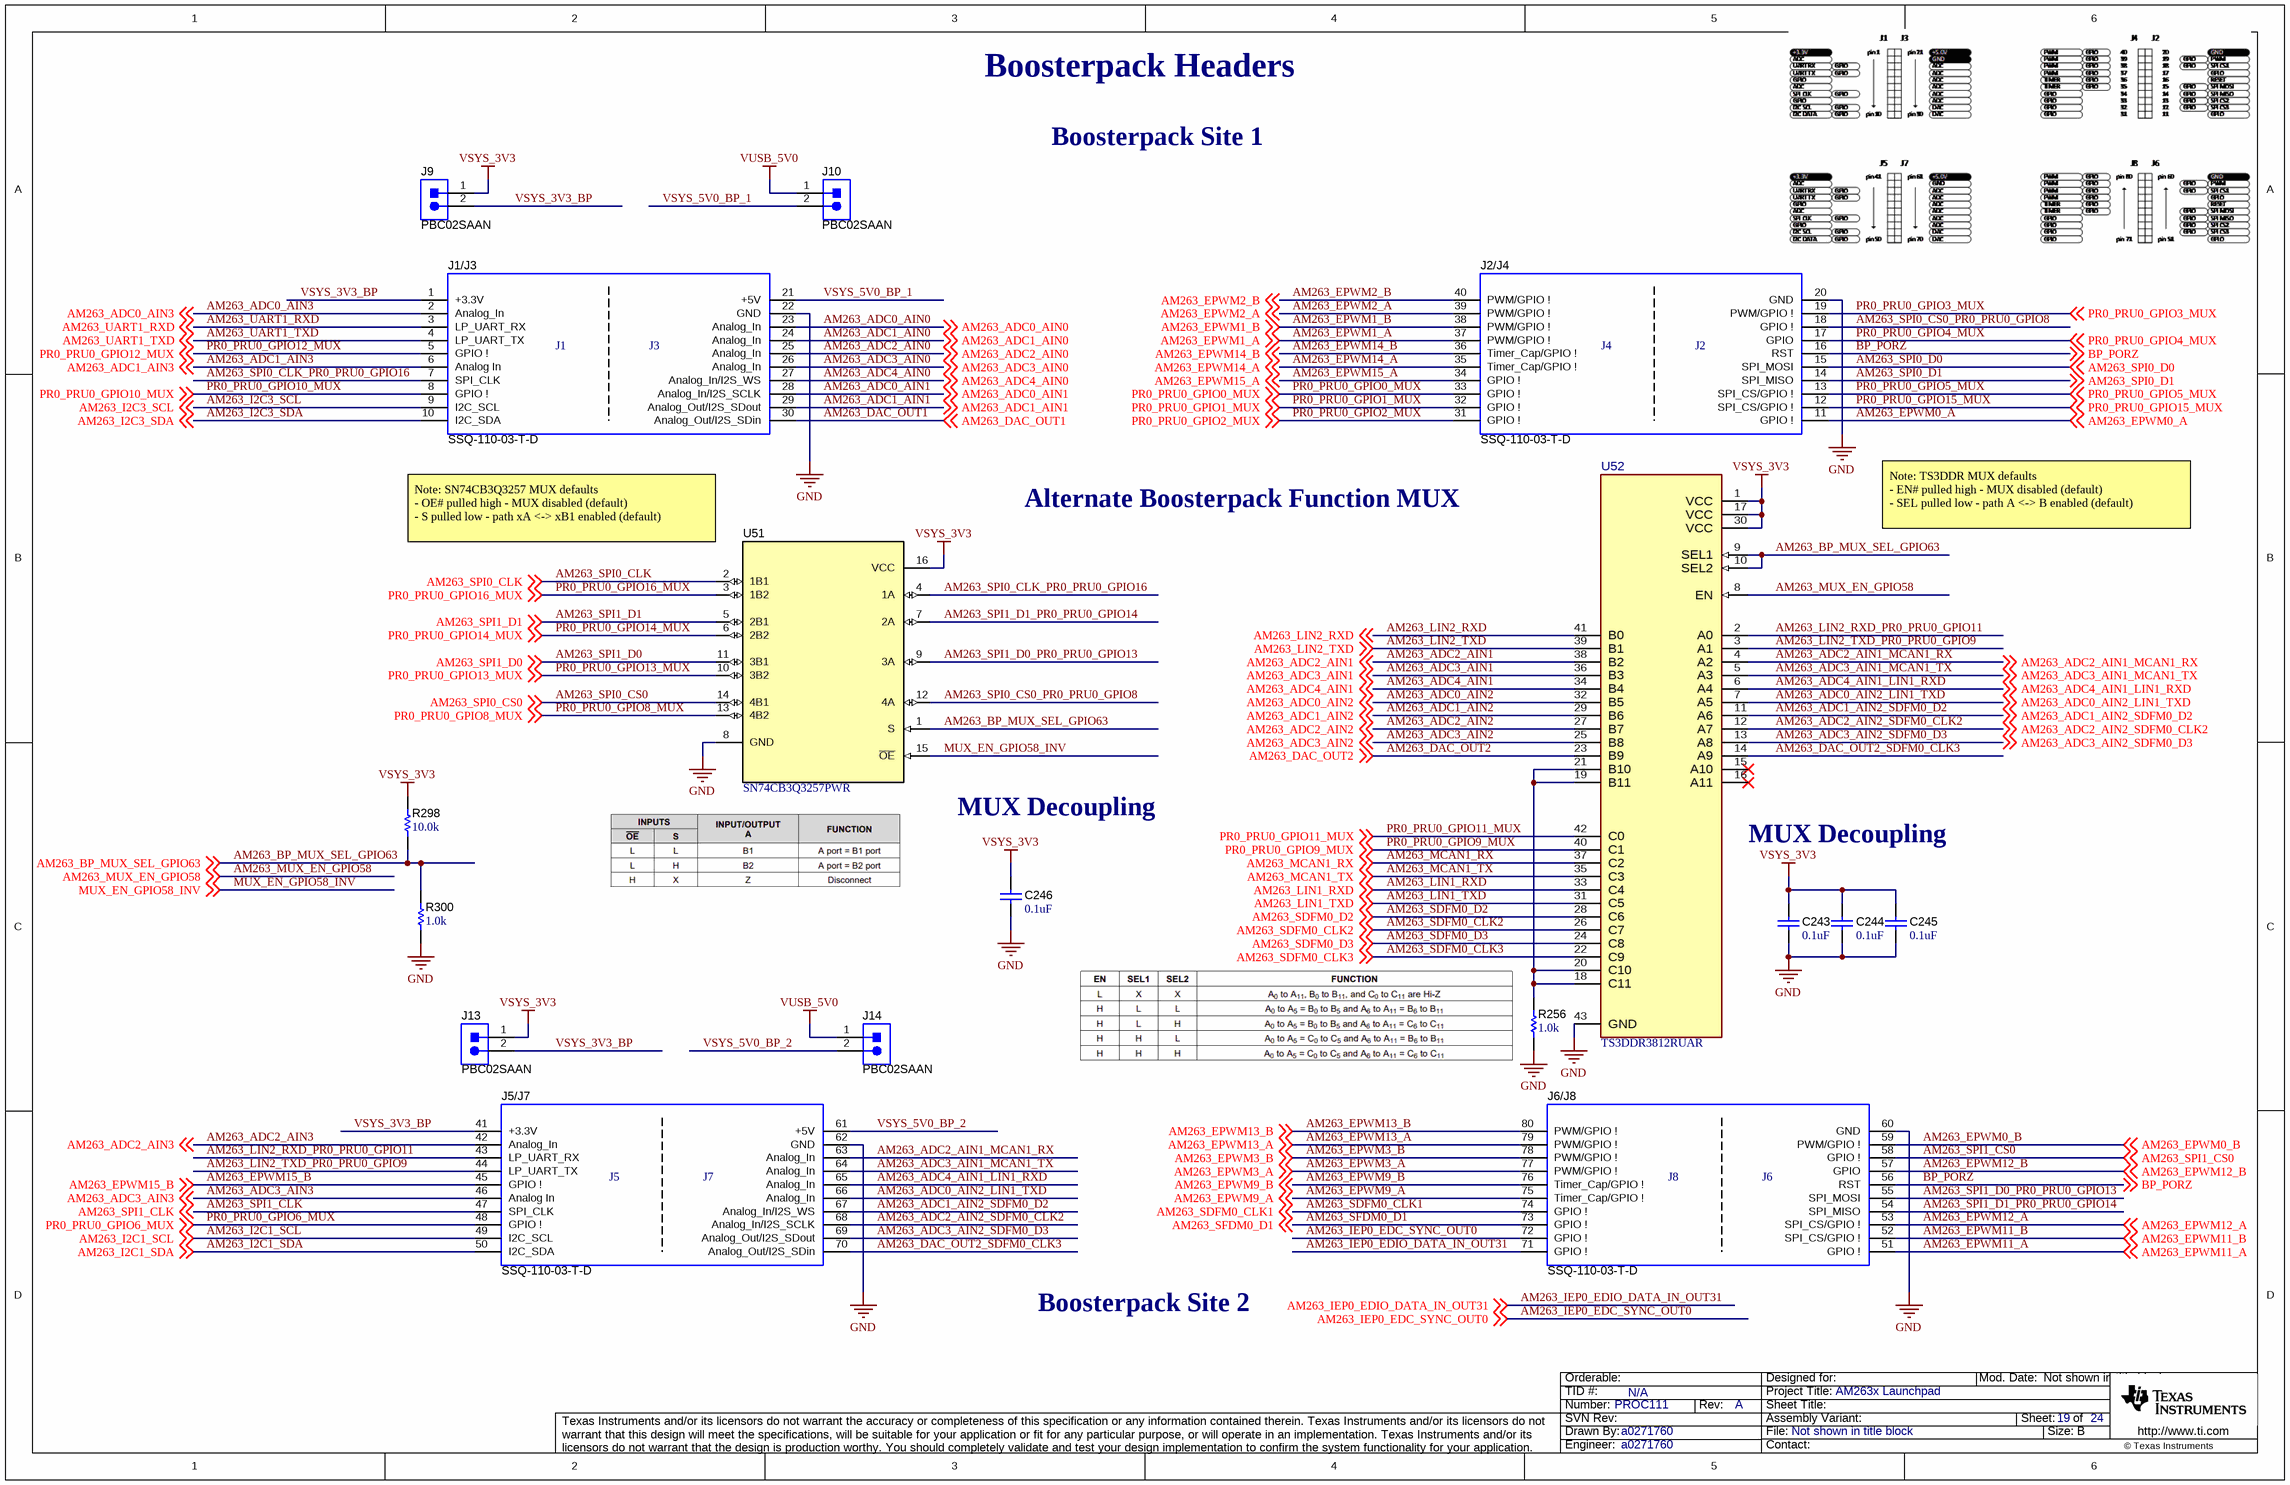
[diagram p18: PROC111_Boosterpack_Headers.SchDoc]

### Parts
C243  ValueDisplayed: 0.1uF  [0402]  (hidden comment: GRM155R71E104KE14D)
C244  ValueDisplayed: 0.1uF  [0402]  (hidden comment: GRM155R71E104KE14D)
C245  ValueDisplayed: 0.1uF  [0402]  (hidden comment: GRM155R71E104KE14D)
C246  ValueDisplayed: 0.1uF  [0402]  (hidden comment: GRM155R71E104KE14D)
J1/J3  SSQ-110-03-T-D  [BoosterPack_40pin_J1J3]
J2/J4  SSQ-110-03-T-D  [BoosterPack_40pin_J2J4]
J5/J7  SSQ-110-03-T-D  [BoosterPack_40pin_J5J7]
J6/J8  SSQ-110-03-T-D  [BoosterPack_40pin_J6J8]
J9  PBC02SAAN  [Sullins_PBC02SAAN]
J10  PBC02SAAN  [Sullins_PBC02SAAN]
J13  PBC02SAAN  [Sullins_PBC02SAAN]
J14  PBC02SAAN  [Sullins_PBC02SAAN]
R256  ValueDisplayed: 1.0k  [0402]  (hidden comment: ERJ-2GEJ102X)
R298  ValueDisplayed: 10.0k  [0402]  (hidden comment: ERJ-2RKF1002X)
R300  ValueDisplayed: 1.0k  [0402]  (hidden comment: ERJ-2GEJ102X)
U51  SN74CB3Q3257PWR  [PW0016A_L]
U52  TS3DDR3812RUAR  [RUA0042A-MFG]

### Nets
GND: C243.1 C244.1 C245.1 C246.1 J1/J3.22(GND) J2/J4.20(GND) J5/J7.62(GND) J6/J8.60(GND) R256.1 R300.1 U51.8(GND) U52.43(GND)
VSYS_3V3: C243.2 C244.2 C245.2 C246.2 J9.1 J13.1 R298.1 U51.16(VCC) U52.1(VCC) U52.17(VCC) U52.30(VCC)
VUSB_5V0: J10.1 J14.1
AM263_ADC0_AIN0: J1/J3.23(Analog_In) ; off-sheet AM263_ADC0_AIN0
AM263_ADC0_AIN1: J1/J3.28(Analog_In/I2S_SCLK) ; off-sheet AM263_ADC0_AIN1
AM263_ADC0_AIN2: U52.32(B5) ; off-sheet AM263_ADC0_AIN2
AM263_ADC0_AIN2_LIN1_TXD: J5/J7.66(Analog_In) U52.7(A5) ; off-sheet AM263_ADC0_AIN2_LIN1_TXD
AM263_ADC0_AIN3: J1/J3.2(Analog_In) ; off-sheet AM263_ADC0_AIN3
AM263_ADC1_AIN0: J1/J3.24(Analog_In) ; off-sheet AM263_ADC1_AIN0
AM263_ADC1_AIN1: J1/J3.29(Analog_Out/I2S_SDout) ; off-sheet AM263_ADC1_AIN1
AM263_ADC1_AIN2: U52.29(B6) ; off-sheet AM263_ADC1_AIN2
AM263_ADC1_AIN2_SDFM0_D2: J5/J7.67(Analog_In/I2S_WS) U52.11(A6) ; off-sheet AM263_ADC1_AIN2_SDFM0_D2
AM263_ADC1_AIN3: J1/J3.6(Analog_In) ; off-sheet AM263_ADC1_AIN3
AM263_ADC2_AIN0: J1/J3.25(Analog_In) ; off-sheet AM263_ADC2_AIN0
AM263_ADC2_AIN1: U52.38(B2) ; off-sheet AM263_ADC2_AIN1
AM263_ADC2_AIN1_MCAN1_RX: J5/J7.63(Analog_In) U52.4(A2) ; off-sheet AM263_ADC2_AIN1_MCAN1_RX
AM263_ADC2_AIN2: U52.27(B7) ; off-sheet AM263_ADC2_AIN2
AM263_ADC2_AIN2_SDFM0_CLK2: J5/J7.68(Analog_In/I2S_SCLK) U52.12(A7) ; off-sheet AM263_ADC2_AIN2_SDFM0_CLK2
AM263_ADC2_AIN3: J5/J7.42(Analog_In) ; off-sheet AM263_ADC2_AIN3
AM263_ADC3_AIN0: J1/J3.26(Analog_In) ; off-sheet AM263_ADC3_AIN0
AM263_ADC3_AIN1: U52.36(B3) ; off-sheet AM263_ADC3_AIN1
AM263_ADC3_AIN1_MCAN1_TX: J5/J7.64(Analog_In) U52.5(A3) ; off-sheet AM263_ADC3_AIN1_MCAN1_TX
AM263_ADC3_AIN2: U52.25(B8) ; off-sheet AM263_ADC3_AIN2
AM263_ADC3_AIN2_SDFM0_D3: J5/J7.69(Analog_Out/I2S_SDout) U52.13(A8) ; off-sheet AM263_ADC3_AIN2_SDFM0_D3
AM263_ADC3_AIN3: J5/J7.46(Analog_In) ; off-sheet AM263_ADC3_AIN3
AM263_ADC4_AIN0: J1/J3.27(Analog_In/I2S_WS) ; off-sheet AM263_ADC4_AIN0
AM263_ADC4_AIN1: U52.34(B4) ; off-sheet AM263_ADC4_AIN1
AM263_ADC4_AIN1_LIN1_RXD: J5/J7.65(Analog_In) U52.6(A4) ; off-sheet AM263_ADC4_AIN1_LIN1_RXD
AM263_BP_MUX_SEL_GPIO63: R298.2 R300.2 U51.1(S) U52.9(SEL1) U52.10(SEL2) ; off-sheet AM263_BP_MUX_SEL_GPIO63
AM263_DAC_OUT1: J1/J3.30(Analog_Out/I2S_SDin) ; off-sheet AM263_DAC_OUT1
AM263_DAC_OUT2: U52.23(B9) ; off-sheet AM263_DAC_OUT2
AM263_DAC_OUT2_SDFM0_CLK3: J5/J7.70(Analog_Out/I2S_SDin) U52.14(A9)
AM263_EPWM0_A: J2/J4.11(GPIO_!) ; off-sheet AM263_EPWM0_A
AM263_EPWM0_B: J6/J8.59(PWM/GPIO_!) ; off-sheet AM263_EPWM0_B
AM263_EPWM1_A: J2/J4.37(PWM/GPIO_!) ; off-sheet AM263_EPWM1_A
AM263_EPWM1_B: J2/J4.38(PWM/GPIO_!) ; off-sheet AM263_EPWM1_B
AM263_EPWM2_A: J2/J4.39(PWM/GPIO_!) ; off-sheet AM263_EPWM2_A
AM263_EPWM2_B: J2/J4.40(PWM/GPIO_!) ; off-sheet AM263_EPWM2_B
AM263_EPWM3_A: J6/J8.77(PWM/GPIO_!) ; off-sheet AM263_EPWM3_A
AM263_EPWM3_B: J6/J8.78(PWM/GPIO_!) ; off-sheet AM263_EPWM3_B
AM263_EPWM9_A: J6/J8.75(Timer_Cap/GPIO_!) ; off-sheet AM263_EPWM9_A
AM263_EPWM9_B: J6/J8.76(Timer_Cap/GPIO_!) ; off-sheet AM263_EPWM9_B
AM263_EPWM11_A: J6/J8.51(GPIO_!) ; off-sheet AM263_EPWM11_A
AM263_EPWM11_B: J6/J8.52(SPI_CS/GPIO_!) ; off-sheet AM263_EPWM11_B
AM263_EPWM12_A: J6/J8.53(SPI_CS/GPIO_!) ; off-sheet AM263_EPWM12_A
AM263_EPWM12_B: J6/J8.57(GPIO) ; off-sheet AM263_EPWM12_B
AM263_EPWM13_A: J6/J8.79(PWM/GPIO_!) ; off-sheet AM263_EPWM13_A
AM263_EPWM13_B: J6/J8.80(PWM/GPIO_!) ; off-sheet AM263_EPWM13_B
AM263_EPWM14_A: J2/J4.35(Timer_Cap/GPIO_!) ; off-sheet AM263_EPWM14_A
AM263_EPWM14_B: J2/J4.36(Timer_Cap/GPIO_!) ; off-sheet AM263_EPWM14_B
AM263_EPWM15_A: J2/J4.34(GPIO_!) ; off-sheet AM263_EPWM15_A
AM263_EPWM15_B: J5/J7.45(GPIO_!) ; off-sheet AM263_EPWM15_B
AM263_I2C1_SCL: J5/J7.49(I2C_SCL) ; off-sheet AM263_I2C1_SCL
AM263_I2C1_SDA: J5/J7.50(I2C_SDA) ; off-sheet AM263_I2C1_SDA
AM263_I2C3_SCL: J1/J3.9(I2C_SCL) ; off-sheet AM263_I2C3_SCL
AM263_I2C3_SDA: J1/J3.10(I2C_SDA) ; off-sheet AM263_I2C3_SDA
AM263_IEP0_EDC_SYNC_OUT0: J6/J8.72(GPIO_!) ; off-sheet AM263_IEP0_EDC_SYNC_OUT0
AM263_IEP0_EDIO_DATA_IN_OUT31: J6/J8.71(GPIO_!) ; off-sheet AM263_IEP0_EDIO_DATA_IN_OUT31
AM263_LIN1_RXD: U52.33(C4) ; off-sheet AM263_LIN1_RXD
AM263_LIN1_TXD: U52.31(C5) ; off-sheet AM263_LIN1_TXD
AM263_LIN2_RXD: U52.41(B0) ; off-sheet AM263_LIN2_RXD
AM263_LIN2_RXD_PR0_PRU0_GPIO11: J5/J7.43(LP_UART_RX) U52.2(A0)
AM263_LIN2_TXD: U52.39(B1) ; off-sheet AM263_LIN2_TXD
AM263_LIN2_TXD_PR0_PRU0_GPIO9: J5/J7.44(LP_UART_TX) U52.3(A1)
AM263_MCAN1_RX: U52.37(C2) ; off-sheet AM263_MCAN1_RX
AM263_MCAN1_TX: U52.35(C3) ; off-sheet AM263_MCAN1_TX
AM263_MUX_EN_GPIO58: U52.8(EN) ; off-sheet AM263_MUX_EN_GPIO58
AM263_SDFM0_CLK1: J6/J8.74(GPIO_!) ; off-sheet AM263_SDFM0_CLK1
AM263_SDFM0_CLK2: U52.26(C7) ; off-sheet AM263_SDFM0_CLK2
AM263_SDFM0_CLK3: U52.22(C9) ; off-sheet AM263_SDFM0_CLK3
AM263_SDFM0_D2: U52.28(C6) ; off-sheet AM263_SDFM0_D2
AM263_SDFM0_D3: U52.24(C8) ; off-sheet AM263_SDFM0_D3
AM263_SFDM0_D1: J6/J8.73(GPIO_!) ; off-sheet AM263_SFDM0_D1
AM263_SPI0_CLK: U51.2(1B1) ; off-sheet AM263_SPI0_CLK
AM263_SPI0_CLK_PR0_PRU0_GPIO16: J1/J3.7(SPI_CLK) U51.4(1A)
AM263_SPI0_CS0: U51.14(4B1) ; off-sheet AM263_SPI0_CS0
AM263_SPI0_CS0_PR0_PRU0_GPIO8: J2/J4.18(GPIO_!) U51.12(4A)
AM263_SPI0_D0: J2/J4.15(SPI_MOSI) ; off-sheet AM263_SPI0_D0
AM263_SPI0_D1: J2/J4.14(SPI_MISO) ; off-sheet AM263_SPI0_D1
AM263_SPI1_CLK: J5/J7.47(SPI_CLK) ; off-sheet AM263_SPI1_CLK
AM263_SPI1_CS0: J6/J8.58(GPIO_!) ; off-sheet AM263_SPI1_CS0
AM263_SPI1_D0: U51.11(3B1) ; off-sheet AM263_SPI1_D0
AM263_SPI1_D0_PR0_PRU0_GPIO13: J6/J8.55(SPI_MOSI) U51.9(3A)
AM263_SPI1_D1: U51.5(2B1) ; off-sheet AM263_SPI1_D1
AM263_SPI1_D1_PR0_PRU0_GPIO14: J6/J8.54(SPI_MISO) U51.7(2A)
AM263_UART1_RXD: J1/J3.3(LP_UART_RX) ; off-sheet AM263_UART1_RXD
AM263_UART1_TXD: J1/J3.4(LP_UART_TX) ; off-sheet AM263_UART1_TXD
BP_PORZ: J2/J4.16(RST) J6/J8.56(RST) ; off-sheet BP_PORZ
MUX_EN_GPIO58_INV: U51.15(~{OE}) ; off-sheet MUX_EN_GPIO58_INV
PR0_PRU0_GPIO0_MUX: J2/J4.33(GPIO_!) ; off-sheet PR0_PRU0_GPIO0_MUX
PR0_PRU0_GPIO1_MUX: J2/J4.32(GPIO_!) ; off-sheet PR0_PRU0_GPIO1_MUX
PR0_PRU0_GPIO2_MUX: J2/J4.31(GPIO_!) ; off-sheet PR0_PRU0_GPIO2_MUX
PR0_PRU0_GPIO3_MUX: J2/J4.19(PWM/GPIO_!) ; off-sheet PR0_PRU0_GPIO3_MUX
PR0_PRU0_GPIO4_MUX: J2/J4.17(GPIO) ; off-sheet PR0_PRU0_GPIO4_MUX
PR0_PRU0_GPIO5_MUX: J2/J4.13(SPI_CS/GPIO_!) ; off-sheet PR0_PRU0_GPIO5_MUX
PR0_PRU0_GPIO6_MUX: J5/J7.48(GPIO_!) ; off-sheet PR0_PRU0_GPIO6_MUX
PR0_PRU0_GPIO8_MUX: U51.13(4B2) ; off-sheet PR0_PRU0_GPIO8_MUX
PR0_PRU0_GPIO9_MUX: U52.40(C1) ; off-sheet PR0_PRU0_GPIO9_MUX
PR0_PRU0_GPIO10_MUX: J1/J3.8(GPIO_!) ; off-sheet PR0_PRU0_GPIO10_MUX
PR0_PRU0_GPIO11_MUX: U52.42(C0) ; off-sheet PR0_PRU0_GPIO11_MUX
PR0_PRU0_GPIO12_MUX: J1/J3.5(GPIO_!) ; off-sheet PR0_PRU0_GPIO12_MUX
PR0_PRU0_GPIO13_MUX: U51.10(3B2) ; off-sheet PR0_PRU0_GPIO13_MUX
PR0_PRU0_GPIO14_MUX: U51.6(2B2) ; off-sheet PR0_PRU0_GPIO14_MUX
PR0_PRU0_GPIO15_MUX: J2/J4.12(SPI_CS/GPIO_!) ; off-sheet PR0_PRU0_GPIO15_MUX
PR0_PRU0_GPIO16_MUX: U51.3(1B2) ; off-sheet PR0_PRU0_GPIO16_MUX
VSYS_3V3_BP: J1/J3.1(+3.3V) J5/J7.41(+3.3V) J9.2 J13.2
VSYS_5V0_BP_1: J1/J3.21(+5V) J10.2
VSYS_5V0_BP_2: J5/J7.61(+5V) J14.2
NetR256_2: R256.2 U52.18(C11) U52.19(B11) U52.20(C10) U52.21(B10)

Not connected (* = marked no-connect by the designer): U52 15(A10)* 16(A11)*

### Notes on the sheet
- Boosterpack Headers
- Boosterpack Site 1
- (near J1/J3) J1
- (near J1/J3) J3
- (near J2/J4) J4
- (near J2/J4) J2
- Note: SN74CB3Q3257 MUX defaults
  - OE# pulled high - MUX disabled (default)
  - S pulled low - path xA <-> xB1 enabled (default)
- Alternate Boosterpack Function MUX
- Note: TS3DDR MUX defaults
  - EN# pulled high - MUX disabled (default)
  - SEL pulled low - path A <-> B enabled (default)
- MUX Decoupling
- (near U52) MUX Decoupling
- (near J5/J7) J5
- (near J5/J7) J7
- (near J6/J8) J8
- (near J6/J8) J6
- Boosterpack Site 2

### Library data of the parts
C243-C246 = CMP-0006659-2: CAP, CERM, 0.1 uF, 25 V, +/- 10%, X7R, 0402; Manufacturer: MuRata; TaMin_C: -55°C; Polarized: N; SizeAreaWB_mm2: 3; U/M: EA; Value: 0.1uF; TaMax_C: 125°C; SizeZ_mm: 0.6; SizeX_mm: 1; SizeY_mm: 0.5; Value2: 25V; Cap_F: 100nF; AEC Category: Q200; Value1: Unknown
J1/J3 = CMP-0003837-4: Receptacle, 2.54mm, 10x2, Tin, TH; Alternate PartNumber: CRD-081413-A-G; Manufacturer: Samtec; Alternate Manufacturer: Major League Electronics; Note: Booster Pack 40 pin J1 and J3; Green_Lifecycle: Active; Green_REACh: Incomplete
J2/J4 = CMP-0078266-4: Receptacle, 2.54mm, 10x2, Tin, TH; Alternate PartNumber: CRD-081413-A-G; Manufacturer: Samtec; Alternate Manufacturer: Major League Electronics; Note: Booster Pack 40 pin J2 and J4; Green_REACh: Incomplete; Green_Lifecycle: Active
J5/J7 = CMP-0081070-3: Receptacle, 2.54mm, 10x2, Tin, TH; Alternate PartNumber: CRD-081413-A-G; Manufacturer: Samtec; Alternate Manufacturer: Major League Electronics; Note: Booster Pack 40 pin J5 and J7; Green_REACh: Incomplete; Green_Lifecycle: Active
J6/J8 = CMP-0081071-3: Receptacle, 2.54mm, 10x2, Tin, TH; Alternate PartNumber: CRD-081413-A-G; Manufacturer: Samtec; Alternate Manufacturer: Major League Electronics; Note: Booster Pack 40 pin J6 and J8; Green_REACh: Incomplete; Green_Lifecycle: Active
J9 J10 J13 J14 = CMP-0054566-1: Header, 100mil, 2x1, Gold, TH; Manufacturer: Sullins Connector Solutions; CNHeader: TRUE; Current_A: 3A; Green_Lifecycle: Active; Shrouded: N; Gender: Male; Green_REACh: Passed; Voltage_V: 1.8kV; Row_Count: 1; Pitch_mm: 2.54; CT: FALSE; Cert_UL: Y
R256 R300 = CMP-0078193-1: RES, 1.0 k, 5%, 0.1 W, AEC-Q200 Grade 0, 0402; Manufacturer: Panasonic; Value_Code: 1k00; SizeArea_mm2: 0.5; AEC Qualified: Y; AEC Category: Q200; Res_ohm: 1k; Value: 1.0k; SizeZ_mm: 0.6; Green_REACh: Passed; EIA_Code: E24; TempCo: 200 ppm/C; AEC Grade: 0; Power_W: 100mW; VDC_V: 50V; Value2: 0.1W; Green_Lifecycle: Active; U/M: EA; SizeX_mm: 1
R298 = CMP-0026658-1: as R306 on sheet PROC111_Ehernet_PHY_2
U51 = CMP-0076540-1: 4-Bit One-of-2 FET Multiplexer/Demultiplexer 2.5-V/3.3-V Low-Voltage, High-Bandwidth Bus Switch, PW0016A (TSSOP-16); Manufacturer: Texas Instruments; SizeAreaWB_mm2: 58.8; SizeArea_mm2: 32.0; SizeZ_mm: 1.2; SizeY_mm: 5.0; U/M: EA; CompType: IC; SizeX_mm: 6.4
U52 = CMP-0093539-2: IC MUX/DEMUX DDR3 1:2 42WQFN; Manufacturer: Texas Instruments; TaMax_C: +85°C; TaMin_C: -40°C; On State Resistance: 8Ω; SizeZ_mm: 0.8mm; Min Supply Voltage: 3V; Standoff Height: 0mm; Max Supply Voltage: 3.6V; AEC Qualified: No; PositionCount: 12; -3Db Bandwith: 1.675GHz; Nominal Supply Current: 300uA; AEC Category: Q200

## Sheet PROC111_Breakout_Headers.SchDoc
size 431 x 279 mm; Date: Not shown in title block; ApprovedBy: Not shown in title block; CheckedBy: Not shown in title block; Author: Not shown in title block; CompanyName: Not shown in title block; Engineer: Not shown in title block; Organization: Not shown in title block; Address1: Not shown in title block; Address2: Not shown in title block; Address3: Not shown in title block; Address4: Not shown in title block; DocumentNumber: 20; Revision: Use project parameter SCH_Rev; SheetNumber: 20; SheetTotal: 24; PageSetup: Record=PageOptions¦CenterHorizontal=True¦CenterVertical=True¦PrintScale=1.00¦XCorrection=1.00¦YCorrection=1.00¦PrintKind=0¦BorderSize=5000000¦LeftOffset=0¦BottomOffset=0¦Orientation=2¦PaperLength=1000¦PaperWidth=1000¦Scale=100¦PaperSource=15¦PrintQuality=600¦MediaType=1¦DitherType=10¦PaperKind=Letter¦PrintScaleMode=1
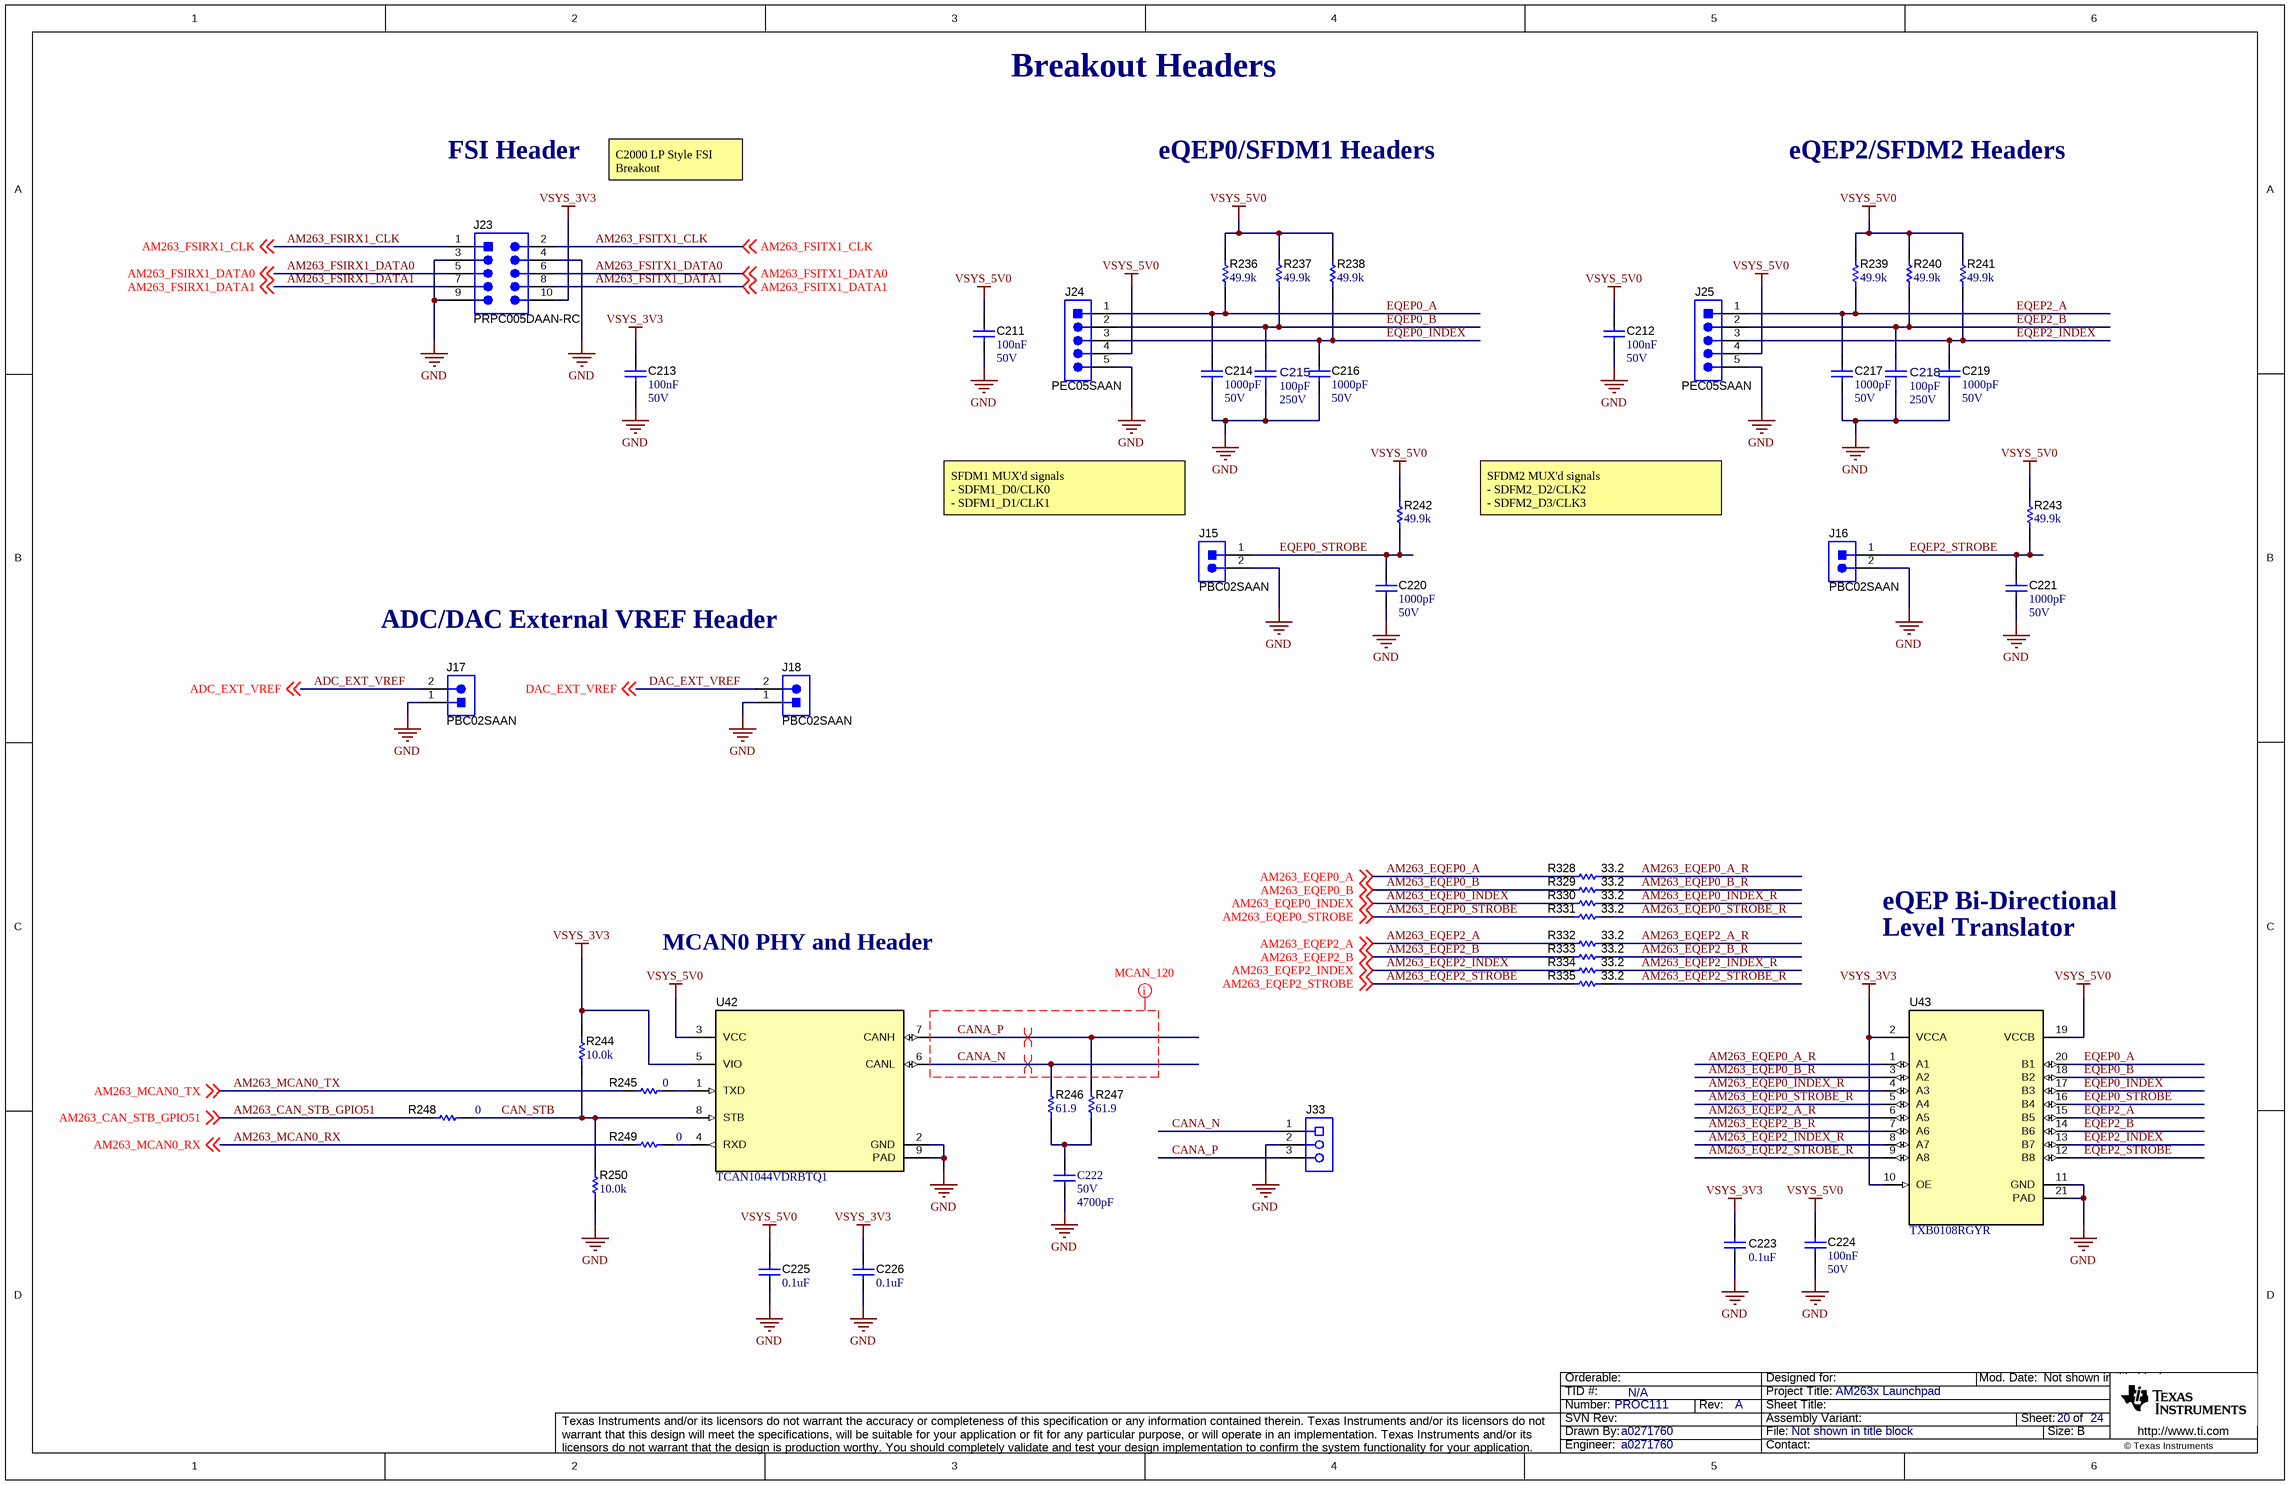
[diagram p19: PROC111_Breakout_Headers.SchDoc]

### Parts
C211  Cap_F: 100nF  VDC_V: 50V  [0603]  (hidden comment: GCM188R71H104KA57D)
C212  Cap_F: 100nF  VDC_V: 50V  [0603]  (hidden comment: GCM188R71H104KA57D)
C213  Cap_F: 100nF  VDC_V: 50V  [0603]  (hidden comment: GCM188R71H104KA57D)
C214  ValueDisplayed: 1000pF  VDC_V: 50V  [0603]  (hidden comment: GCM1885C1H102JA16D)
C215  VDC_V: 250V  ValueDisplayed: 100pF  [FP-GQM1875C2E101JB12D_0603-MFG]  (hidden comment: GQM1875C2E101JB12D)
C216  ValueDisplayed: 1000pF  VDC_V: 50V  [0603]  (hidden comment: GCM1885C1H102JA16D)
C217  ValueDisplayed: 1000pF  VDC_V: 50V  [0603]  (hidden comment: GCM1885C1H102JA16D)
C218  VDC_V: 250V  ValueDisplayed: 100pF  [FP-GQM1875C2E101JB12D_0603-MFG]  (hidden comment: GQM1875C2E101JB12D)
C219  ValueDisplayed: 1000pF  VDC_V: 50V  [0603]  (hidden comment: GCM1885C1H102JA16D)
C220  ValueDisplayed: 1000pF  VDC_V: 50V  [0603]  (hidden comment: GCM1885C1H102JA16D)
C221  ValueDisplayed: 1000pF  VDC_V: 50V  [0603]  (hidden comment: GCM1885C1H102JA16D)
C222  VDC_V: 50V  ValueDisplayed: 4700pF  [0402]  (hidden comment: GCM155R71H472KA37D)
C223  ValueDisplayed: 0.1uF  [0402]  (hidden comment: GRM155R71E104KE14D)
C224  Cap_F: 100nF  VDC_V: 50V  [0603]  (hidden comment: GCM188R71H104KA57D)
C225  ValueDisplayed: 0.1uF  [0402]  (hidden comment: GRM155R71E104KE14D)
C226  ValueDisplayed: 0.1uF  [0402]  (hidden comment: GRM155R71E104KE14D)
J15  PBC02SAAN  [Sullins_PBC02SAAN]
J16  PBC02SAAN  [Sullins_PBC02SAAN]
J17  PBC02SAAN  [Sullins_PBC02SAAN]
J18  PBC02SAAN  [Sullins_PBC02SAAN]
J23  PRPC005DAAN-RC  [Sullins_xxPC005DAAN-RC]
J24  PEC05SAAN  [Sullins_PxC05SAAN]
J25  PEC05SAAN  [Sullins_PxC05SAAN]
J33  OSTTE030161  [On-Shore_OSTTE030161]  (value not drawn)
R236  ValueDisplayed: 49.9k  [0402]  (hidden comment: ERJ-2RKF4992X)
R237  ValueDisplayed: 49.9k  [0402]  (hidden comment: ERJ-2RKF4992X)
R238  ValueDisplayed: 49.9k  [0402]  (hidden comment: ERJ-2RKF4992X)
R239  ValueDisplayed: 49.9k  [0402]  (hidden comment: ERJ-2RKF4992X)
R240  ValueDisplayed: 49.9k  [0402]  (hidden comment: ERJ-2RKF4992X)
R241  ValueDisplayed: 49.9k  [0402]  (hidden comment: ERJ-2RKF4992X)
R242  ValueDisplayed: 49.9k  [0402]  (hidden comment: ERJ-2RKF4992X)
R243  ValueDisplayed: 49.9k  [0402]  (hidden comment: ERJ-2RKF4992X)
R244  ValueDisplayed: 10.0k  [0402L]  (hidden comment: CRCW040210K0FKED)
R245  value 0  [0402L]  (hidden comment: ERJ-2GE0R00X)
R246  ValueDisplayed: 61.9  [0402L]  (hidden comment: CRCW040261R9FKED)
R247  ValueDisplayed: 61.9  [0402L]  (hidden comment: CRCW040261R9FKED)
R248  ValueDisplayed: 0  [0402L]  (hidden comment: ERJ-2GE0R00X)
R249  ValueDisplayed: 0  [0402L]  (hidden comment: ERJ-2GE0R00X)
R250  ValueDisplayed: 10.0k  [0402L]  (hidden comment: CRCW040210K0FKED)
R328  ValueDisplayed: 33.2  [0402]  (hidden comment: CRCW040233R2FKED)
R329  ValueDisplayed: 33.2  [0402]  (hidden comment: CRCW040233R2FKED)
R330  ValueDisplayed: 33.2  [0402]  (hidden comment: CRCW040233R2FKED)
R331  ValueDisplayed: 33.2  [0402]  (hidden comment: CRCW040233R2FKED)
R332  ValueDisplayed: 33.2  [0402]  (hidden comment: CRCW040233R2FKED)
R333  ValueDisplayed: 33.2  [0402]  (hidden comment: CRCW040233R2FKED)
R334  ValueDisplayed: 33.2  [0402]  (hidden comment: CRCW040233R2FKED)
R335  ValueDisplayed: 33.2  [0402]  (hidden comment: CRCW040233R2FKED)
U42  TCAN1044VDRBTQ1  [DRB0008J]
U43  TXB0108RGYR  [RGY0020A]

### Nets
GND: C211.2 C212.2 C213.2 C214.2 C215.1 C216.2 C217.2 C218.1 C219.2 C220.2 C221.2 C222.2 C223.1 C224.2 C225.1 C226.1 J15.2 J16.2 J17.1 J18.1 J23.3 J23.4 J23.9 J24.5 J25.5 J33.2 R250.1 U42.2(GND) U42.9(PAD) U43.11(GND) U43.21(PAD)
VSYS_3V3: C213.1 C223.2 C226.2 J23.10 R244.2 U42.5(VIO) U43.2(VCCA) U43.10(OE)
VSYS_5V0: C211.1 C212.1 C224.1 C225.2 J24.4 J25.4 R236.2 R237.2 R238.2 R239.2 R240.2 R241.2 R242.2 R243.2 U42.3(VCC) U43.19(VCCB)
ADC_EXT_VREF: J17.2 ; off-sheet ADC_EXT_VREF
AM263_CAN_STB_GPIO51: R248.2 ; off-sheet AM263_CAN_STB_GPIO51
AM263_EQEP0_A: R328.1 ; off-sheet AM263_EQEP0_A
AM263_EQEP0_A_R: R328.2 U43.1(A1)
AM263_EQEP0_B: R329.1 ; off-sheet AM263_EQEP0_B
AM263_EQEP0_B_R: R329.2 U43.3(A2)
AM263_EQEP0_INDEX: R330.1 ; off-sheet AM263_EQEP0_INDEX
AM263_EQEP0_INDEX_R: R330.2 U43.4(A3)
AM263_EQEP0_STROBE: R331.1 ; off-sheet AM263_EQEP0_STROBE
AM263_EQEP0_STROBE_R: R331.2 U43.5(A4)
AM263_EQEP2_A: R332.1 ; off-sheet AM263_EQEP2_A
AM263_EQEP2_A_R: R332.2 U43.6(A5)
AM263_EQEP2_B: R333.1 ; off-sheet AM263_EQEP2_B
AM263_EQEP2_B_R: R333.2 U43.7(A6)
AM263_EQEP2_INDEX: R334.1 ; off-sheet AM263_EQEP2_INDEX
AM263_EQEP2_INDEX_R: R334.2 U43.8(A7)
AM263_EQEP2_STROBE: R335.1 ; off-sheet AM263_EQEP2_STROBE
AM263_EQEP2_STROBE_R: R335.2 U43.9(A8)
AM263_FSIRX1_CLK: J23.1 ; off-sheet AM263_FSIRX1_CLK
AM263_FSIRX1_DATA0: J23.5 ; off-sheet AM263_FSIRX1_DATA0
AM263_FSIRX1_DATA1: J23.7 ; off-sheet AM263_FSIRX1_DATA1
AM263_FSITX1_CLK: J23.2 ; off-sheet AM263_FSITX1_CLK
AM263_FSITX1_DATA0: J23.6 ; off-sheet AM263_FSITX1_DATA0
AM263_FSITX1_DATA1: J23.8 ; off-sheet AM263_FSITX1_DATA1
AM263_MCAN0_RX: R249.1 ; off-sheet AM263_MCAN0_RX
AM263_MCAN0_TX: R245.1 ; off-sheet AM263_MCAN0_TX
CAN_STB: R244.1 R248.1 R250.2 U42.8(STB)
CANA_N: J33.1 R246.2 U42.6(CANL)
CANA_P: J33.3 R247.2 U42.7(CANH)
DAC_EXT_VREF: J18.2 ; off-sheet DAC_EXT_VREF
EQEP0_A: C214.1 J24.1 R236.1 U43.20(B1)
EQEP0_B: C215.2 J24.2 R237.1 U43.18(B2)
EQEP0_INDEX: C216.1 J24.3 R238.1 U43.17(B3)
EQEP0_STROBE: C220.1 J15.1 R242.1 U43.16(B4)
EQEP2_A: C217.1 J25.1 R239.1 U43.15(B5)
EQEP2_B: C218.2 J25.2 R240.1 U43.14(B6)
EQEP2_INDEX: C219.1 J25.3 R241.1 U43.13(B7)
EQEP2_STROBE: C221.1 J16.1 R243.1 U43.12(B8)
NetC222_1: C222.1 R246.1 R247.1
NetR245_2: R245.2 U42.1(TXD)
NetR249_2: R249.2 U42.4(RXD)

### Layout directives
differential pair: CANA_N, CANA_P
mark named MCAN_120: CANA_N, CANA_P

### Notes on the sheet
- Breakout Headers
- FSI Header
- eQEP0/SFDM1 Headers
- eQEP2/SFDM2 Headers
- C2000 LP Style FSI Breakout
- SFDM1 MUX'd signals
  - SDFM1_D0/CLK0
  - SDFM1_D1/CLK1
- SFDM2 MUX'd signals
  - SDFM2_D2/CLK2
  - SDFM2_D3/CLK3
- ADC/DAC External VREF Header
- MCAN0 PHY and Header
- eQEP Bi-Directional
- Level Translator

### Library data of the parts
C211-C213 C224 = CMP-0007144-4: CAP, CERM, 0.1 uF, 50 V, +/- 10%, X7R, 0603; Manufacturer: MuRata; TaMin_C: -55°C; ESR_ohm: 20m; Polarized: N; SizeAreaWB_mm2: 4.68; Value1: 0.02 ohm; U/M: EA; Value: 0.1uF; TaMax_C: 125°C; SizeZ_mm: 1; SizeX_mm: 1.6; SizeY_mm: 0.8; SizeArea_mm2: 1.28; IRMS_A: 1.84A; AEC Category: Q200
C214 C216 C217 C219-C221 = CMP-0086079-1: CAP, CERM, 1000 pF, 50 V,+/- 5%, C0G/NP0, AEC-Q200 Grade 1, 0603; Manufacturer: MuRata; Value: 1000pF; U/M: EA; Green_Lifecycle: Active; SizeAreaWB_mm2: 4.68; SizeX_mm: 1.6; SizeZ_mm: 1; AEC Qualified: Y; SizeArea_mm2: 1.28; TaMax_C: 125°C; SizeY_mm: 0.8; Cap_F: 1nF; TaMin_C: -55°C; Green_REACh: Incomplete; AEC Category: Q200; Polarized: N
C215 C218 = CMP-0035320-1: Ceramic Capacitor 100pF ±5% 250VDC C0G 0603 Paper T/R; Manufacturer: Murata; TempCo: 30ppm/°C; Tolerance_%: 0.05%; SizeZ_mm: 0.8mm; AEC Qualified: No
C222 = CMP-0006361-2: CAP, CERM, 4700 pF, 50 V, +/- 10%, X7R, AEC-Q200 Grade 1, 0402; Manufacturer: MuRata; TaMin_C: -55°C; Polarized: N; SizeAreaWB_mm2: 3; Value1: Unknown; U/M: EA; Value: 4700pF; TaMax_C: 125°C; SizeZ_mm: 0.6; SizeX_mm: 1; SizeY_mm: 0.5; AEC Qualified: Y; Cap_F: 4.7nF; AEC Category: Q200
C223 C225 C226 = CMP-0006659-2: as C243-C246 on sheet PROC111_Boosterpack_Headers
J15-J18 = CMP-0054566-1: as J9 on sheet PROC111_Boosterpack_Headers
J23 = CMP-0080722-2: Header, 2.54mm, 5x2, Gold, TH; Manufacturer: Sullins Connector Solutions; Pitch_mm: 2.54; Gender: Male; Cert_UL: Y; Current_A: 3A; Voltage_V: 1kV; Shrouded: N; Row_Count: 2
J24 J25 = CMP-0054597-1: Header, 2.54mm, 5x1, Tin, TH; Manufacturer: Sullins Connector Solutions; CNHeader: TRUE; Current_A: 3A; Green_Lifecycle: Not Set; Shrouded: N; Gender: Male; Green_REACh: Incomplete; Voltage_V: 1.8kV; Row_Count: 1; Pitch_mm: 2.54; CT: FALSE; Cert_UL: Y
J33 = CMP-0075352-1: Terminal Block, 3.5mm, 3x1, Tin, R/A, TH; Manufacturer: On-Shore Technology; CNHeader: False; Current_A: 10A; Green_Lifecycle: Not Set; Gender: Female; Cert_CSA: Y; Green_REACh: Incomplete; Voltage_V: 125V; Row_Count: 1; Pitch_mm: 3.5; CT: True
R236-R243 = CMP-0026702-1: RES, 49.9 k, 1%, 0.1 W, AEC-Q200 Grade 0, 0402; Manufacturer: Panasonic; Power_W: 100mW; TempCo: 100 ppm/C; Value_Code: 49k9; U/M: EA; Value: 49.9k; EIA_Code: E96; SizeX_mm: 1; SizeY_mm: 0.5; SizeZ_mm: 0.6; Value2: 0.1W; AEC Qualified: Y; VDC_V: 50V; AEC Grade: 0; AEC Category: Q200
R244 R250 = CMP-0025958-3: RES, 10.0 k, 1%, 0.063 W, AEC-Q200 Grade 0, 0402; Manufacturer: Vishay-Dale; Power_W: 63mW; TempCo: 100 ppm/C; Value_Code: 10k0; Value: 10.0k; EIA_Code: E96; Res_ohm: 10k; SizeX_mm: 1; SizeY_mm: 0.5; SizeZ_mm: 0.6; Value2: 0.063W; AEC Qualified: Y; VDC_V: 50V; AEC Category: Q200; AEC Grade: 0
R245 = CMP-0026992-3: RES, 0, 5%, 0.1 W, AEC-Q200 Grade 0, 0402; Manufacturer: Panasonic; Power_W: 100mW; TempCo: 600 ppm/C; Value_Code: 0000; EIA_Code: E24; SizeX_mm: 1; SizeY_mm: 0.5; SizeZ_mm: 0.6; Value2: 0.1W; AEC Qualified: Y; VDC_V: 50V; AEC Category: Q200; SizeAreaWB_mm2: 3
R246 R247 = CMP-0026491-2: RES, 61.9, 1%, 0.063 W, AEC-Q200 Grade 0, 0402; Manufacturer: Vishay-Dale; Power_W: 63mW; TempCo: 100 ppm/C; Value_Code: 61R9; Value: 61.9; EIA_Code: E96; SizeX_mm: 1; SizeY_mm: 0.5; SizeZ_mm: 0.6; Value2: 0.063W; AEC Qualified: Y; VDC_V: 50V; AEC Category: Q200; AEC Grade: 0
R248 R249 = CMP-0026992-3: as R196-R201 on sheet PROC111_Ehernet_PHY_2
R328-R335 = CMP-0026299-2: RES, 33.2, 1%, 0.063 W, AEC-Q200 Grade 0, 0402; Manufacturer: Vishay-Dale; Power_W: 63mW; TempCo: 100 ppm/C; Value_Code: 33R2; Value: 33.2; EIA_Code: E96; SizeX_mm: 1; SizeY_mm: 0.5; SizeZ_mm: 0.6; Value2: 0.063W; AEC Qualified: Y; VDC_V: 50V; AEC Category: Q200; AEC Grade: 0
U42 = CMP-0079884-2: Automotive High Speed CAN Transceiver, DRB0008J (VSON-8); Alternate Manufacturer: Texas Instruments; Alternate PartNumber: TCAN1044VDRBRQ1; SizeX_mm: 3; AEC Category: Q200; SizeAreaWB_mm2: 16; SizeZ_mm: 1; SizeArea_mm2: 9; AEC Qualified: Y; CompType: IC
U43 = CMP-0074359-2: 8-Bit Bidirectional Voltage-Level Shifter with Auto Direction Sensing and +/-15-kV ESD Protect, RGY0020A (VQFN-20); Manufacturer: Texas Instruments; SizeZ_mm: 1.0; SizeX_mm: 3.5; SizeY_mm: 4.5; SizeArea_mm2: 15.75; CompType: IC; U/M: EA; SizeAreaWB_mm2: 24.75

## Sheet PROC111_XDS110_1.SchDoc: XDS110 JTAG/USB-to-UART Bridge
size 431 x 279 mm; Date: Not shown in title block; ApprovedBy: Not shown in title block; CheckedBy: Not shown in title block; Author: Not shown in title block; CompanyName: Not shown in title block; Engineer: Not shown in title block; Organization: Not shown in title block; Address1: Not shown in title block; Address2: Not shown in title block; Address3: Not shown in title block; Address4: Not shown in title block; DocumentNumber: 21; Revision: Use project parameter SCH_Rev; SheetNumber: 21; SheetTotal: 24; PageSetup: Record=PageOptions¦CenterHorizontal=True¦CenterVertical=True¦PrintScale=1.00¦XCorrection=1.00¦YCorrection=1.00¦PrintKind=0¦BorderSize=5000000¦LeftOffset=0¦BottomOffset=0¦Orientation=2¦PaperLength=1000¦PaperWidth=1000¦Scale=100¦PaperSource=15¦PrintQuality=600¦MediaType=1¦DitherType=10¦PaperKind=Letter¦PrintScaleMode=1
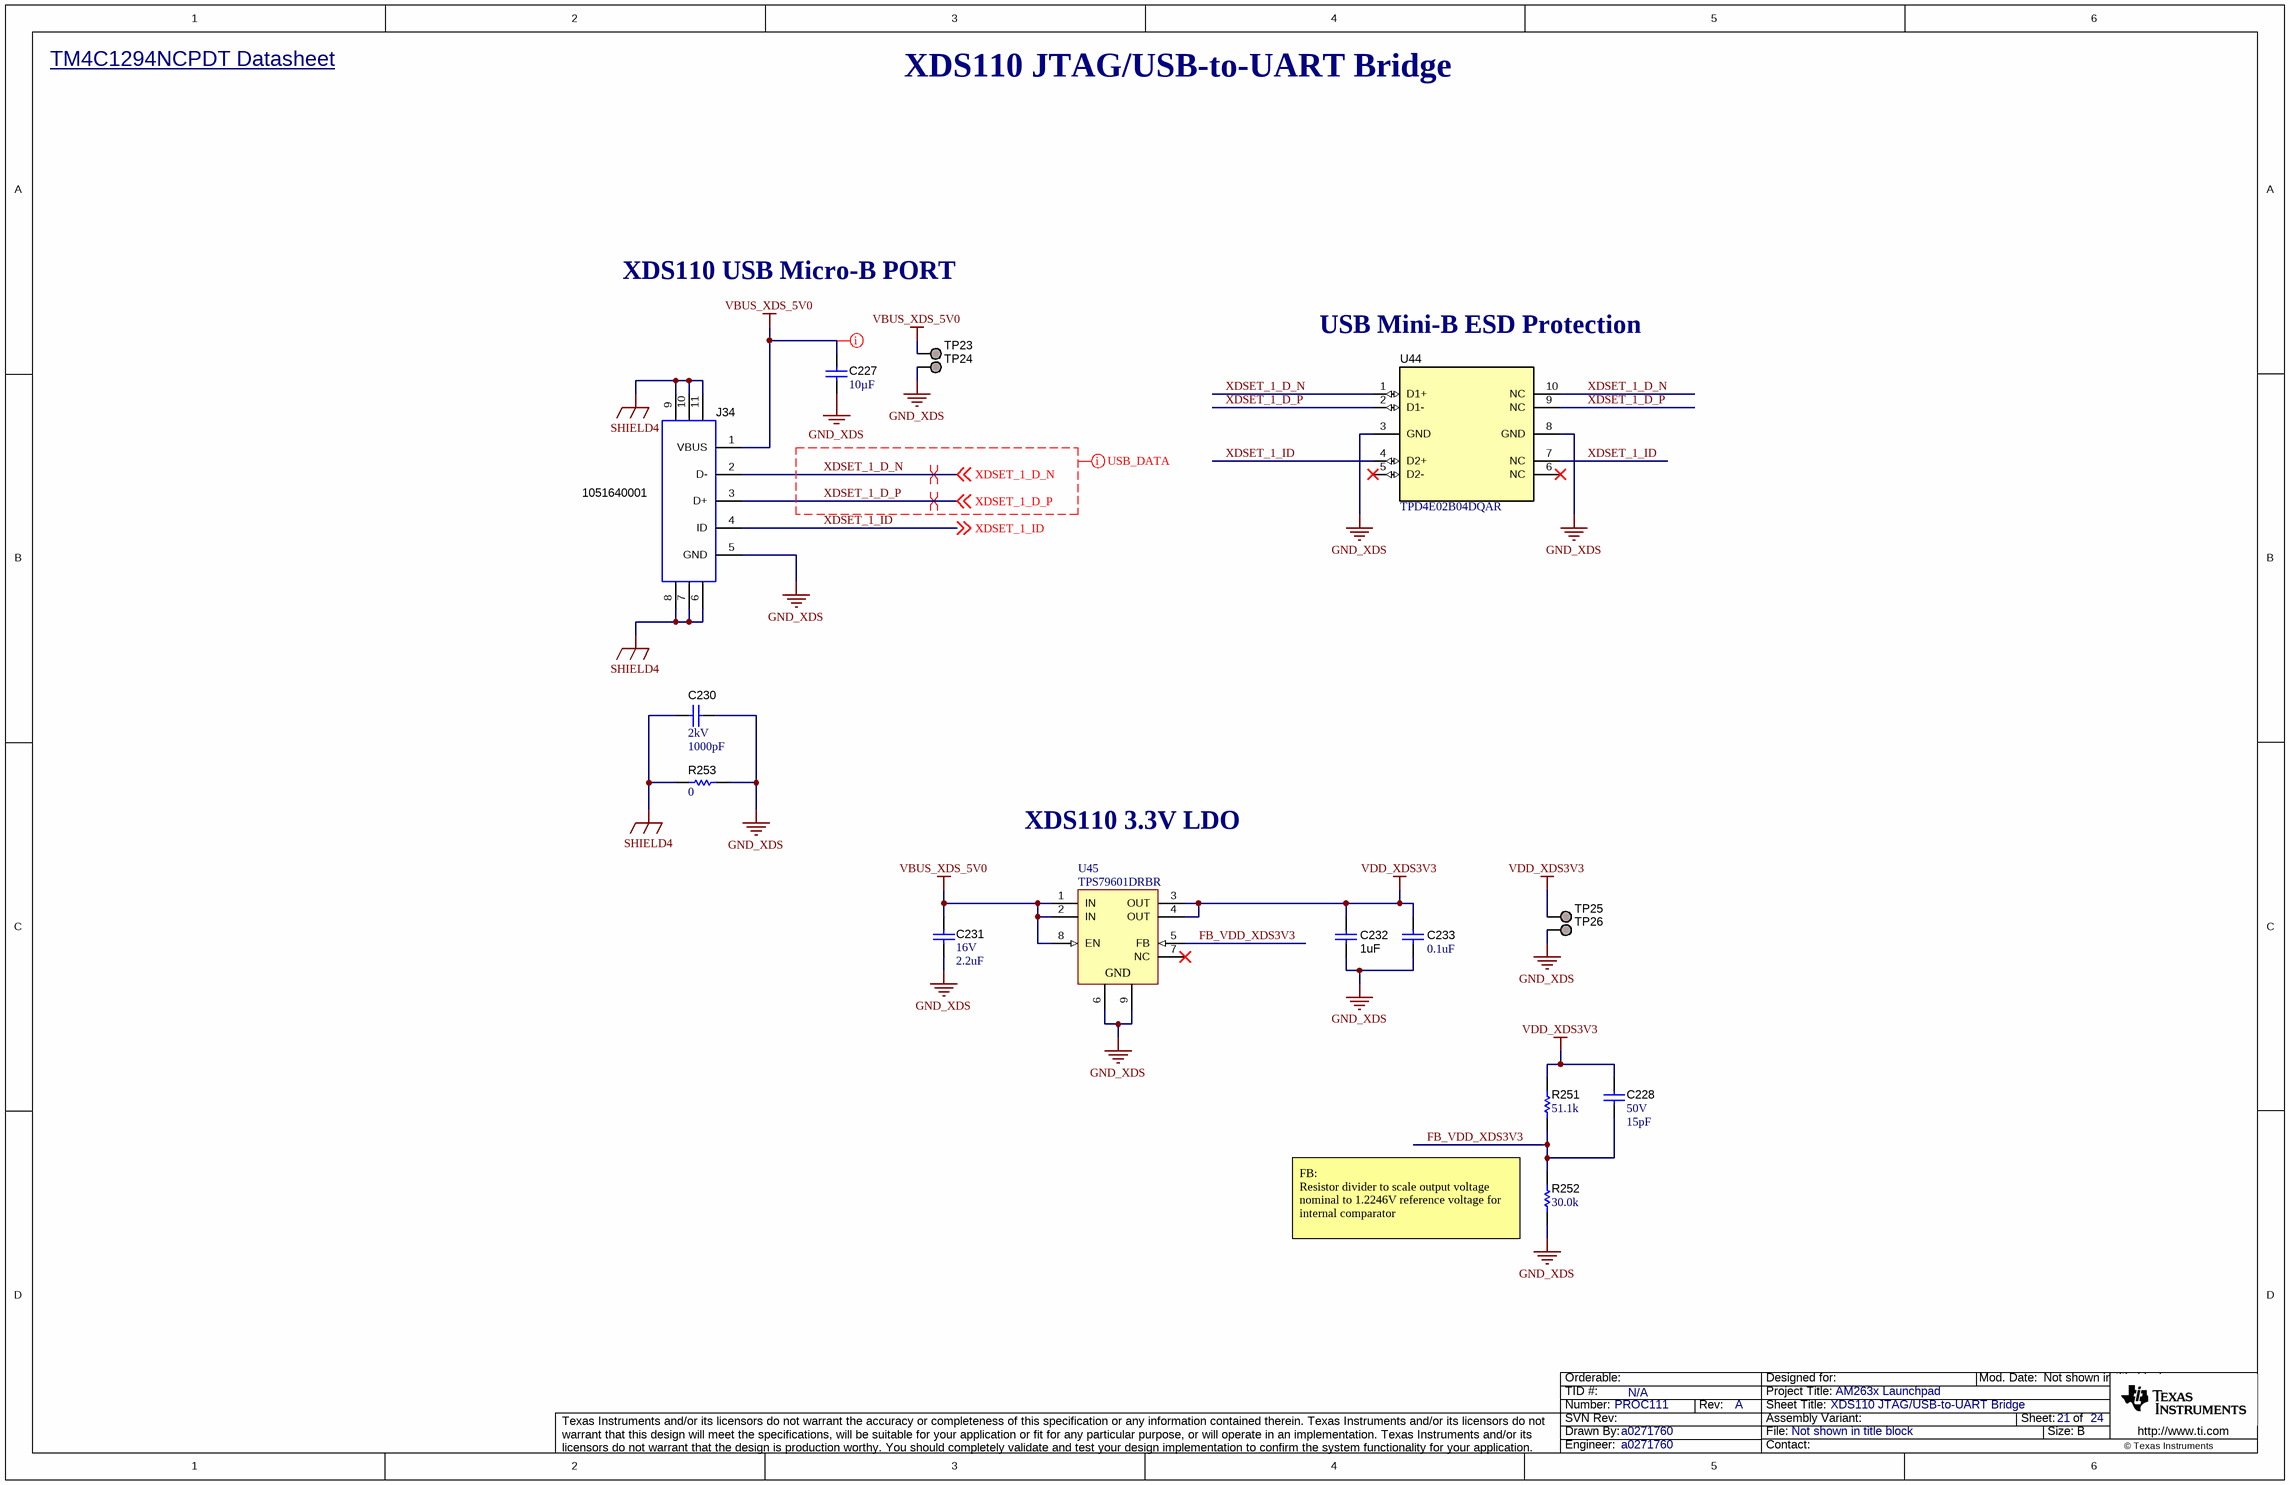
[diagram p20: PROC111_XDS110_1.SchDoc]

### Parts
C227  Cap_F: 10µF  [0805_HV]  (hidden comment: GRM21BZ71E106KE15L)
C228  VDC_V: 50V  ValueDisplayed: 15pF  [0402]  (hidden comment: GRM1555C1H150JA01D)
C230  VDC_V: 2kV  ValueDisplayed: 1000pF  [1808]  (hidden comment: GR442QR73D102KW01L)
C231  VDC_V: 16V  ValueDisplayed: 2.2uF  [0402]  (hidden comment: GRM155C81C225KE11D)
C232  ValueDisplayed: 1uF  [0402_070]  (hidden comment: GCM155C71A105KE38D)
C233  ValueDisplayed: 0.1uF  [0402]  (hidden comment: GRM155R71E104KE14D)
J34  1051640001  [Molex_1051640001]
R251  ValueDisplayed: 51.1k  [0402]  (hidden comment: CRCW040251K1FKED)
R252  ValueDisplayed: 30.0k  [0402]  (hidden comment: CRCW040230K0FKED)
R253  ValueDisplayed: 0  [0805_HV]  (hidden comment: ERJ-6GEY0R00V)
TP23  TESTPOINT  [TP_25MIL-SMT]  (value not drawn)  (no BOM)
TP24  TESTPOINT  [TP_25MIL-SMT]  (value not drawn)  (no BOM)
TP25  TESTPOINT  [TP_25MIL-SMT]  (value not drawn)  (no BOM)
TP26  TESTPOINT  [TP_25MIL-SMT]  (value not drawn)  (no BOM)
U44  TPD4E02B04DQAR  [DQA0010A]
U45  TPS79601DRBR  [DRB0008B]

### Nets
GND_XDS: C227.2 C230.1 C231.2 C232.2 C233.1 J34.5(GND) R252.1 R253.2 TP24.1 TP26.1 U44.3(GND) U44.8(GND) U45.6(GND) U45.9(GND)
SHIELD4: C230.2 J34.6 J34.7 J34.8 J34.9 J34.10 J34.11 R253.1
VBUS_XDS_5V0: C227.1 C231.1 J34.1(VBUS) TP23.1 U45.1(IN) U45.2(IN) U45.8(EN)
VDD_XDS3V3: C228.1 C232.1 C233.2 R251.2 TP25.1 U45.3(OUT) U45.4(OUT)
FB_VDD_XDS3V3: C228.2 R251.1 R252.2 U45.5(FB)
XDSET_1_D_N: J34.2(D-) U44.1(D1+) U44.10(NC) ; off-sheet XDSET_1_D_N
XDSET_1_D_P: J34.3(D+) U44.2(D1-) U44.9(NC) ; off-sheet XDSET_1_D_P
XDSET_1_ID: J34.4(ID) U44.4(D2+) U44.7(NC) ; off-sheet XDSET_1_ID

Not connected (* = marked no-connect by the designer): U44 5(D2-)* 6(NC)*; U45 7(NC)*

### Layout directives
differential pair: XDSET_1_D_N, XDSET_1_D_P
net class POWER: VBUS_XDS_5V0
mark named USB_DATA: XDSET_1_D_N, XDSET_1_D_P

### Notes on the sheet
- TM4C1294NCPDT Datasheet <http://www.ti.com/lit/ds/symlink/tm4c1294ncpdt.pdf>
- XDS110 JTAG/USB-to-UART Bridge
- XDS110 USB Micro-B PORT
- USB Mini-B ESD Protection
- XDS110 3.3V LDO
- (near R252) FB:
  Resistor divider to scale output voltage nominal to 1.2246V reference voltage for internal comparator

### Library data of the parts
C227 = CMP-0008378-2: CAP, CERM, 10 uF, 25 V, +/- 10%, X7R, 0805; Manufacturer: MuRata; TaMin_C: -55°C; Polarized: N; SizeAreaWB_mm2: 6.75; Value1: Unknown; U/M: EA; Value: 10uF; TaMax_C: 125°C; SizeZ_mm: 1.45; SizeX_mm: 2; SizeY_mm: 1.25; Cap_Case: 0805; Value2: 25V; SizeArea_mm2: 2.5; AEC Category: Q200
C228 = CMP-0006420-2: CAP, CERM, 15 pF, 50 V, +/- 5%, C0G/NP0, 0402; Manufacturer: MuRata; TaMin_C: -55°C; Polarized: N; SizeAreaWB_mm2: 3; Value1: Unknown; U/M: EA; Value: 15pF; TaMax_C: 125°C; SizeZ_mm: 0.6; SizeX_mm: 1; SizeY_mm: 0.5; AEC Category: Q200
C230 = CMP-0009436-2: as C235 on sheet PROC111_Ehernet_RJ45_1
C231 = CMP-0006526-2: CAP, CERM, 2.2 uF, 16 V, +/- 10%, X6S, 0402; Manufacturer: MuRata; TaMin_C: -55°C; Polarized: N; SizeAreaWB_mm2: 3; Value1: Unknown; U/M: EA; Value: 2.2uF; TaMax_C: 105°C; SizeZ_mm: 0.6; SizeX_mm: 1; SizeY_mm: 0.5; Cap_F: 2.2µF; AEC Category: Q200
C232 = CMP-0006349-2: CAP, CERM, 1 uF, 10 V, +/- 10%, X7S, AEC-Q200 Grade 1, 0402; Manufacturer: MuRata; TaMin_C: -55°C; Polarized: N; SizeAreaWB_mm2: 3; Value1: Unknown; U/M: EA; Value: 1uF; TaMax_C: 125°C; SizeZ_mm: 0.7; SizeX_mm: 1; SizeY_mm: 0.5; Cap_Case: 0402; Value2: 10V; AEC Qualified: Y; Cap_F: 1µF; AEC Category: Q200
C233 = CMP-0006659-2: as C243-C246 on sheet PROC111_Boosterpack_Headers
J34 = CMP-0055311-1: Receptacle, USB 2.0, Micro B, 5 Position, R/A, SMT; Manufacturer: Molex; CNHeader: FALSE; Current_A: 1.8A; Gender: Female; Voltage_V: 30V; Pitch_mm: 0.65; ContactFinish: Gold; CT: TRUE; Cert_UL: Y
R251 = CMP-0026437-2: RES, 51.1 k, 1%, 0.063 W, AEC-Q200 Grade 0, 0402; Manufacturer: Vishay-Dale; Power_W: 63mW; TempCo: 100 ppm/C; Value_Code: 51k1; Value: 51.1k; EIA_Code: E96; SizeX_mm: 1; SizeY_mm: 0.5; SizeZ_mm: 0.6; Value2: 0.063W; AEC Qualified: Y; VDC_V: 50V; AEC Category: Q200; AEC Grade: 0
R252 = CMP-0078244-2: RES, 30.0 k, 1%, 0.063 W, AEC-Q200 Grade 0, 0402; Manufacturer: Vishay-Dale; Power_W: 63mW; Green_Lifecycle: Active; TempCo: 100 ppm/C; Value_Code: 30k0; Green_REACh: Passed; Value: 30.0k; Res_ohm: 30k; SizeX_mm: 1; SizeY_mm: 0.5; SizeZ_mm: 0.6; Value2: 0.063W; AEC Qualified: Y; VDC_V: 50V; AEC Grade: 0; AEC Category: Q200
R253 = CMP-0020616-3: RES, 0, 5%, 0.125 W, AEC-Q200 Grade 0, 0805; Manufacturer: Panasonic; Power_W: 125mW; TempCo: 600 ppm/C; Value_Code: 0000; Value: 0; EIA_Code: E24; SizeX_mm: 2; SizeY_mm: 1.25; SizeZ_mm: 1.45; Value2: 0.125W; SizeArea_mm2: 2.5; AEC Qualified: Y; VDC_V: 150V; AEC Category: Q200; SizeAreaWB_mm2: 6.75
TP23-TP26 = CMP-0078143-3: TEST POINT.  No entry in BOM.
U44 = CMP-0073612-3: 4-Channel ESD Protection Diode for USB Type-C and HDMI 2.0, DQA0010A (USON-10); Alternate Manufacturer: Texas Instruments; Green_Lifecycle: Active; SizeAreaWB_mm2: 7.0; Green_REACh: Passed; SizeZ_mm: 0.55; SizeX_mm: 1.0; SizeY_mm: 2.5; CompType: IC; AEC Category: Q200; AEC Qualified: Y
U45 = CMP-0036402-3: Single Output High PSRR LDO, 1 A, Adjustable 1.2 to 5.5 V Output, 2.7 to 5.5 V Input, 8-pin SON (DRB), -40 to 125 degC, Green (RoHS & no Sb/Br); Manufacturer: Texas Instruments; Vin(Min)(V): 2.7; Vout Adj(Max)(V): 5.5; Vout Adj(Min)(V): 1.2; Accuracy(%): 2; SubFamily: Single Channel LDO; Iq(Typ)(mA): 0.26; Vdo(Typ)(mV): 250; Iout(Max)(A): 1; AEC Category: Q200; AEC Qualified: N; CompType: IC; SizeAreaWB_mm2: 16.0; SizeArea_mm2: 9.0; SizeX_mm: 3.0; SizeZ_mm: 1.0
